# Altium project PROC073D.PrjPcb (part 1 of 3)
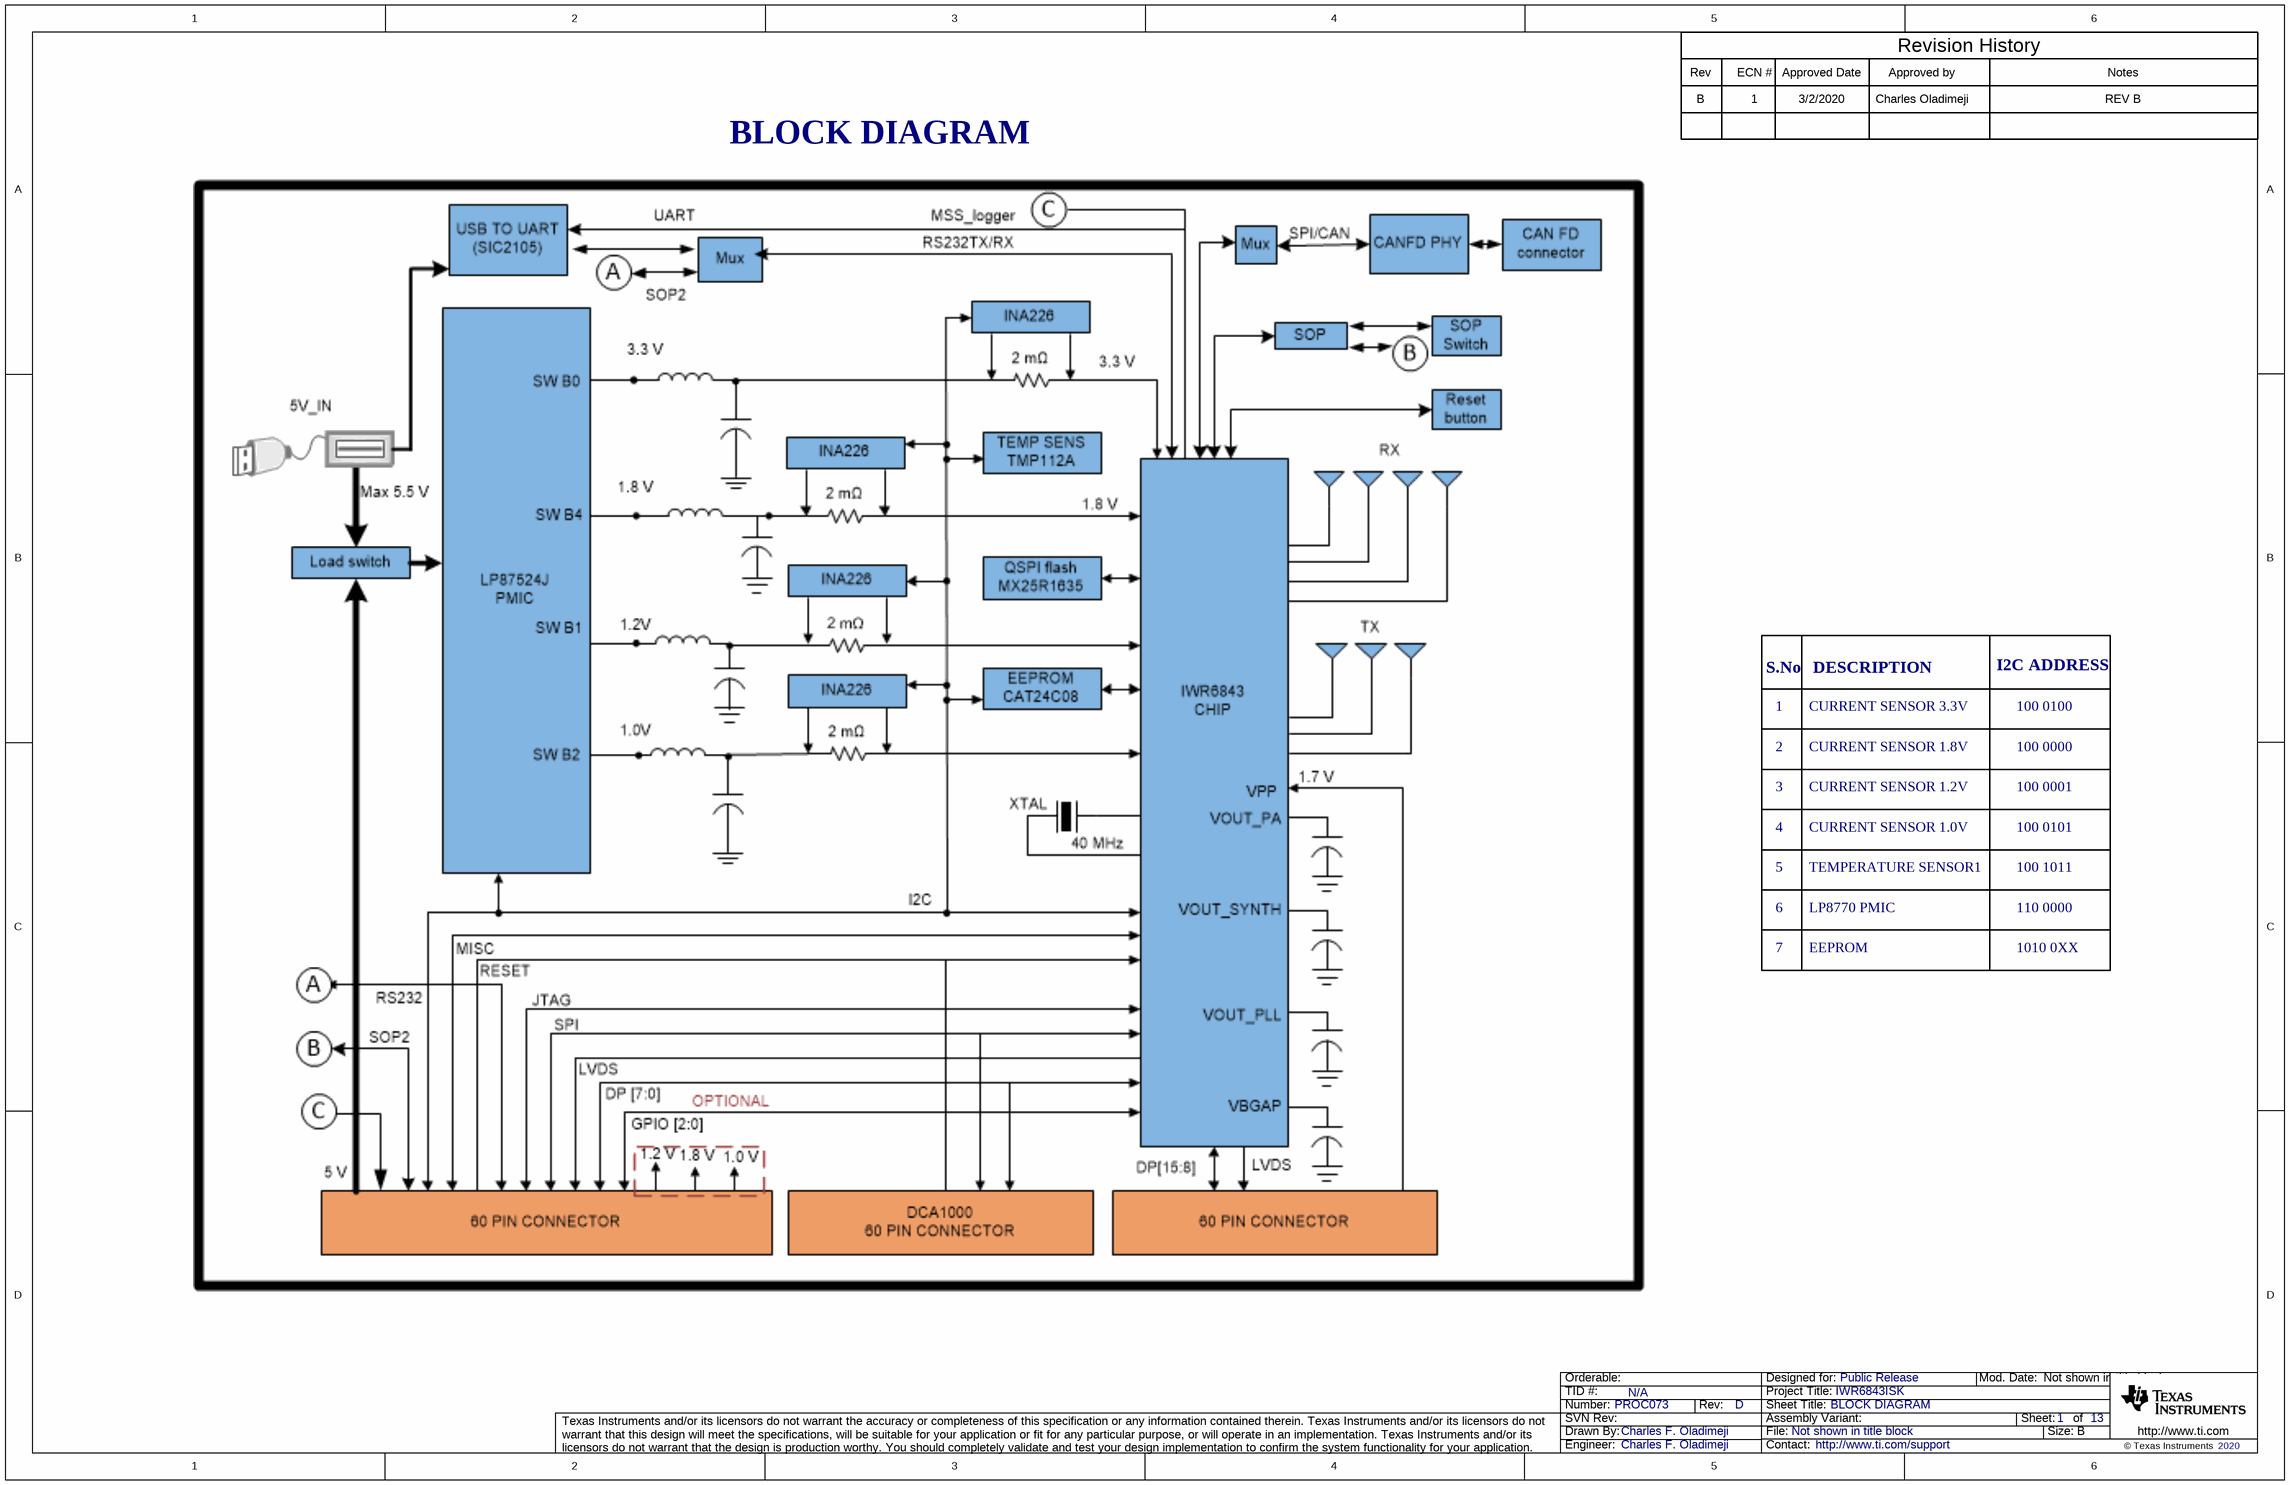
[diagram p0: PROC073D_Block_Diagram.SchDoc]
CopyrightYear: 2020; PCB_Layout: Tessolve; PCB_Rev: D; PRJ_Customer: Public Release; PRJ_Engineer: Charles F. Oladimeji; PRJ_Number: PROC073; PRJ_Title: IWR6843ISK; SCH_Rev: D; TechSupport: http://www.ti.com/support; TID: N/A
13 sheets, 431 parts. Net scope: flat (ports and power ports of the same name join across sheets).
Board file: PROC073D_PCB.PcbDoc
Sheets:
  PROC073D_Block_Diagram.SchDoc
  PROC073D_Table_Of_Contents.SchDoc
  PROC073D_PMIC.SchDoc
  PROC073D_IWR6843_Chip.SchDoc
  PROC073D_Decoupling_caps.SchDoc
  PROC073D_QSPI_Flash_section.SchDoc
  PROC073D_HD_Connector_60Pin.SchDoc
  PROC073D_Temp_Current_sensor.SchDoc
  PROC073D_Flash_USB_To_UART.SchDoc
  PROC073D_HD_DCA_Conn.SchDoc
  PROC073D_SOP_Ctrl.SchDoc
  PROC073D_Can_Interface.SchDoc
  PROC073D_EVM_Hardware.SchDoc

## Sheet PROC073D_Block_Diagram.SchDoc: BLOCK DIAGRAM
size 431 x 279 mm; Date: Not shown in title block; ApprovedBy: Not shown in title block; CheckedBy: Not shown in title block; Author: Not shown in title block; CompanyName: Not shown in title block; DrawnBy: Charles F. Oladimeji; Engineer: Not shown in title block; Organization: Not shown in title block; Address1: Not shown in title block; Address2: Not shown in title block; Address3: Not shown in title block; Address4: Not shown in title block; DocumentNumber: 1; Revision: Use project parameter SCH_Rev; SheetNumber: 1; SheetTotal: 13; PageSetup: Record=PageOptions¦CenterHorizontal=True¦CenterVertical=True¦PrintScale=1.00¦XCorrection=1.00¦YCorrection=1.00¦PrintKind=0¦BorderSize=5000000¦LeftOffset=0¦BottomOffset=0¦Orientation=2¦PaperLength=1000¦PaperWidth=1000¦Scale=100¦PaperSource=15¦PrintQuality=600¦MediaType=1¦DitherType=10¦PaperKind=Letter¦PrintScaleMode=1

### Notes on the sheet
- Rev
- B
- ECN #
- 1
- Approved Date
- 3/2/2020
- Approved by
- Charles Oladimeji
- Revision History
- Notes
- REV B
- BLOCK DIAGRAM
- S.No
- DESCRIPTION
- I2C ADDRESS
- 2
- CURRENT SENSOR 3.3V
- CURRENT SENSOR 1.8V
- 100 0100
- 100 0000
- 3
- 4
- CURRENT SENSOR 1.2V
- CURRENT SENSOR 1.0V
- 100 0001
- 100 0101
- 5
- TEMPERATURE SENSOR1
- 100 1011
- 6
- 7
- LP8770 PMIC
- EEPROM
- 1010 0XX
- 110 0000

## Sheet PROC073D_Table_Of_Contents.SchDoc: TABLE OF CONTENTS
size 431 x 279 mm; Date: Not shown in title block; ApprovedBy: Not shown in title block; CheckedBy: Not shown in title block; Author: Not shown in title block; CompanyName: Not shown in title block; DrawnBy: Charles F. Oladimeji; Engineer: Not shown in title block; Organization: Not shown in title block; Address1: Not shown in title block; Address2: Not shown in title block; Address3: Not shown in title block; Address4: Not shown in title block; DocumentNumber: 2; Revision: Use project parameter SCH_Rev; SheetNumber: 2; SheetTotal: 13; PageSetup: Record=PageOptions¦CenterHorizontal=True¦CenterVertical=True¦PrintScale=1.00¦XCorrection=1.00¦YCorrection=1.00¦PrintKind=0¦BorderSize=5000000¦LeftOffset=0¦BottomOffset=0¦Orientation=2¦PaperLength=1000¦PaperWidth=1000¦Scale=100¦PaperSource=15¦PrintQuality=600¦MediaType=1¦DitherType=10¦PaperKind=Letter¦PrintScaleMode=1
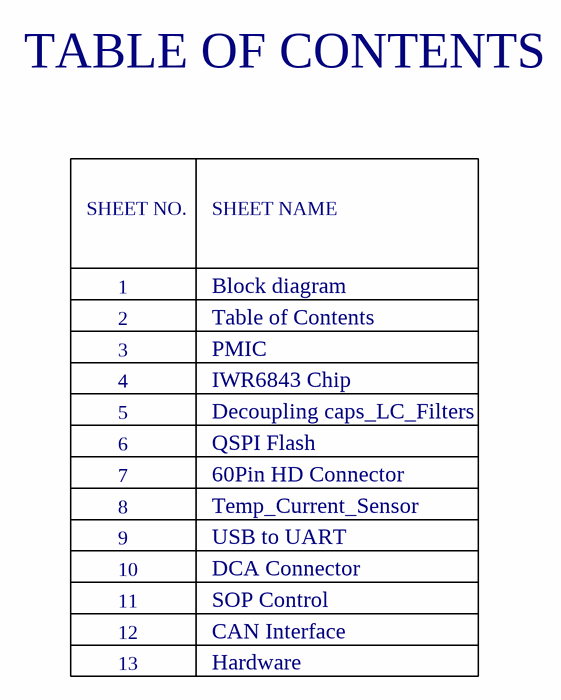
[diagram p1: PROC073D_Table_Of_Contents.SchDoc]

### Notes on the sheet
- TABLE OF CONTENTS
- SHEET NO.
- SHEET NAME
- 1
- 2
- 3
- Table of Contents
- Block diagram
- PMIC
- 4
- 5
- IWR6843 Chip
- Decoupling caps_LC_Filters
- 7
- 8
- 6
- QSPI Flash
- 60Pin HD Connector
- Temp_Current_Sensor
- 9
- 10
- USB to UART
- DCA Connector
- 11
- 12
- 13
- SOP Control
- CAN Interface
- Hardware

## Sheet PROC073D_PMIC.SchDoc: PMIC
size 431 x 279 mm; Date: Not shown in title block; ApprovedBy: Not shown in title block; CheckedBy: Not shown in title block; Author: Not shown in title block; CompanyName: Not shown in title block; DrawnBy: Charles F. Oladimeji; Engineer: Not shown in title block; Organization: Not shown in title block; Address1: Not shown in title block; Address2: Not shown in title block; Address3: Not shown in title block; Address4: Not shown in title block; DocumentNumber: 3; Revision: Use project parameter SCH_Rev; SheetNumber: 3; SheetTotal: 13; PageSetup: Record=PageOptions¦CenterHorizontal=True¦CenterVertical=True¦PrintScale=1.00¦XCorrection=1.00¦YCorrection=1.00¦PrintKind=0¦BorderSize=5000000¦LeftOffset=0¦BottomOffset=0¦Orientation=2¦PaperLength=1000¦PaperWidth=1000¦Scale=100¦PaperSource=15¦PrintQuality=600¦MediaType=1¦DitherType=10¦PaperKind=Letter¦PrintScaleMode=1
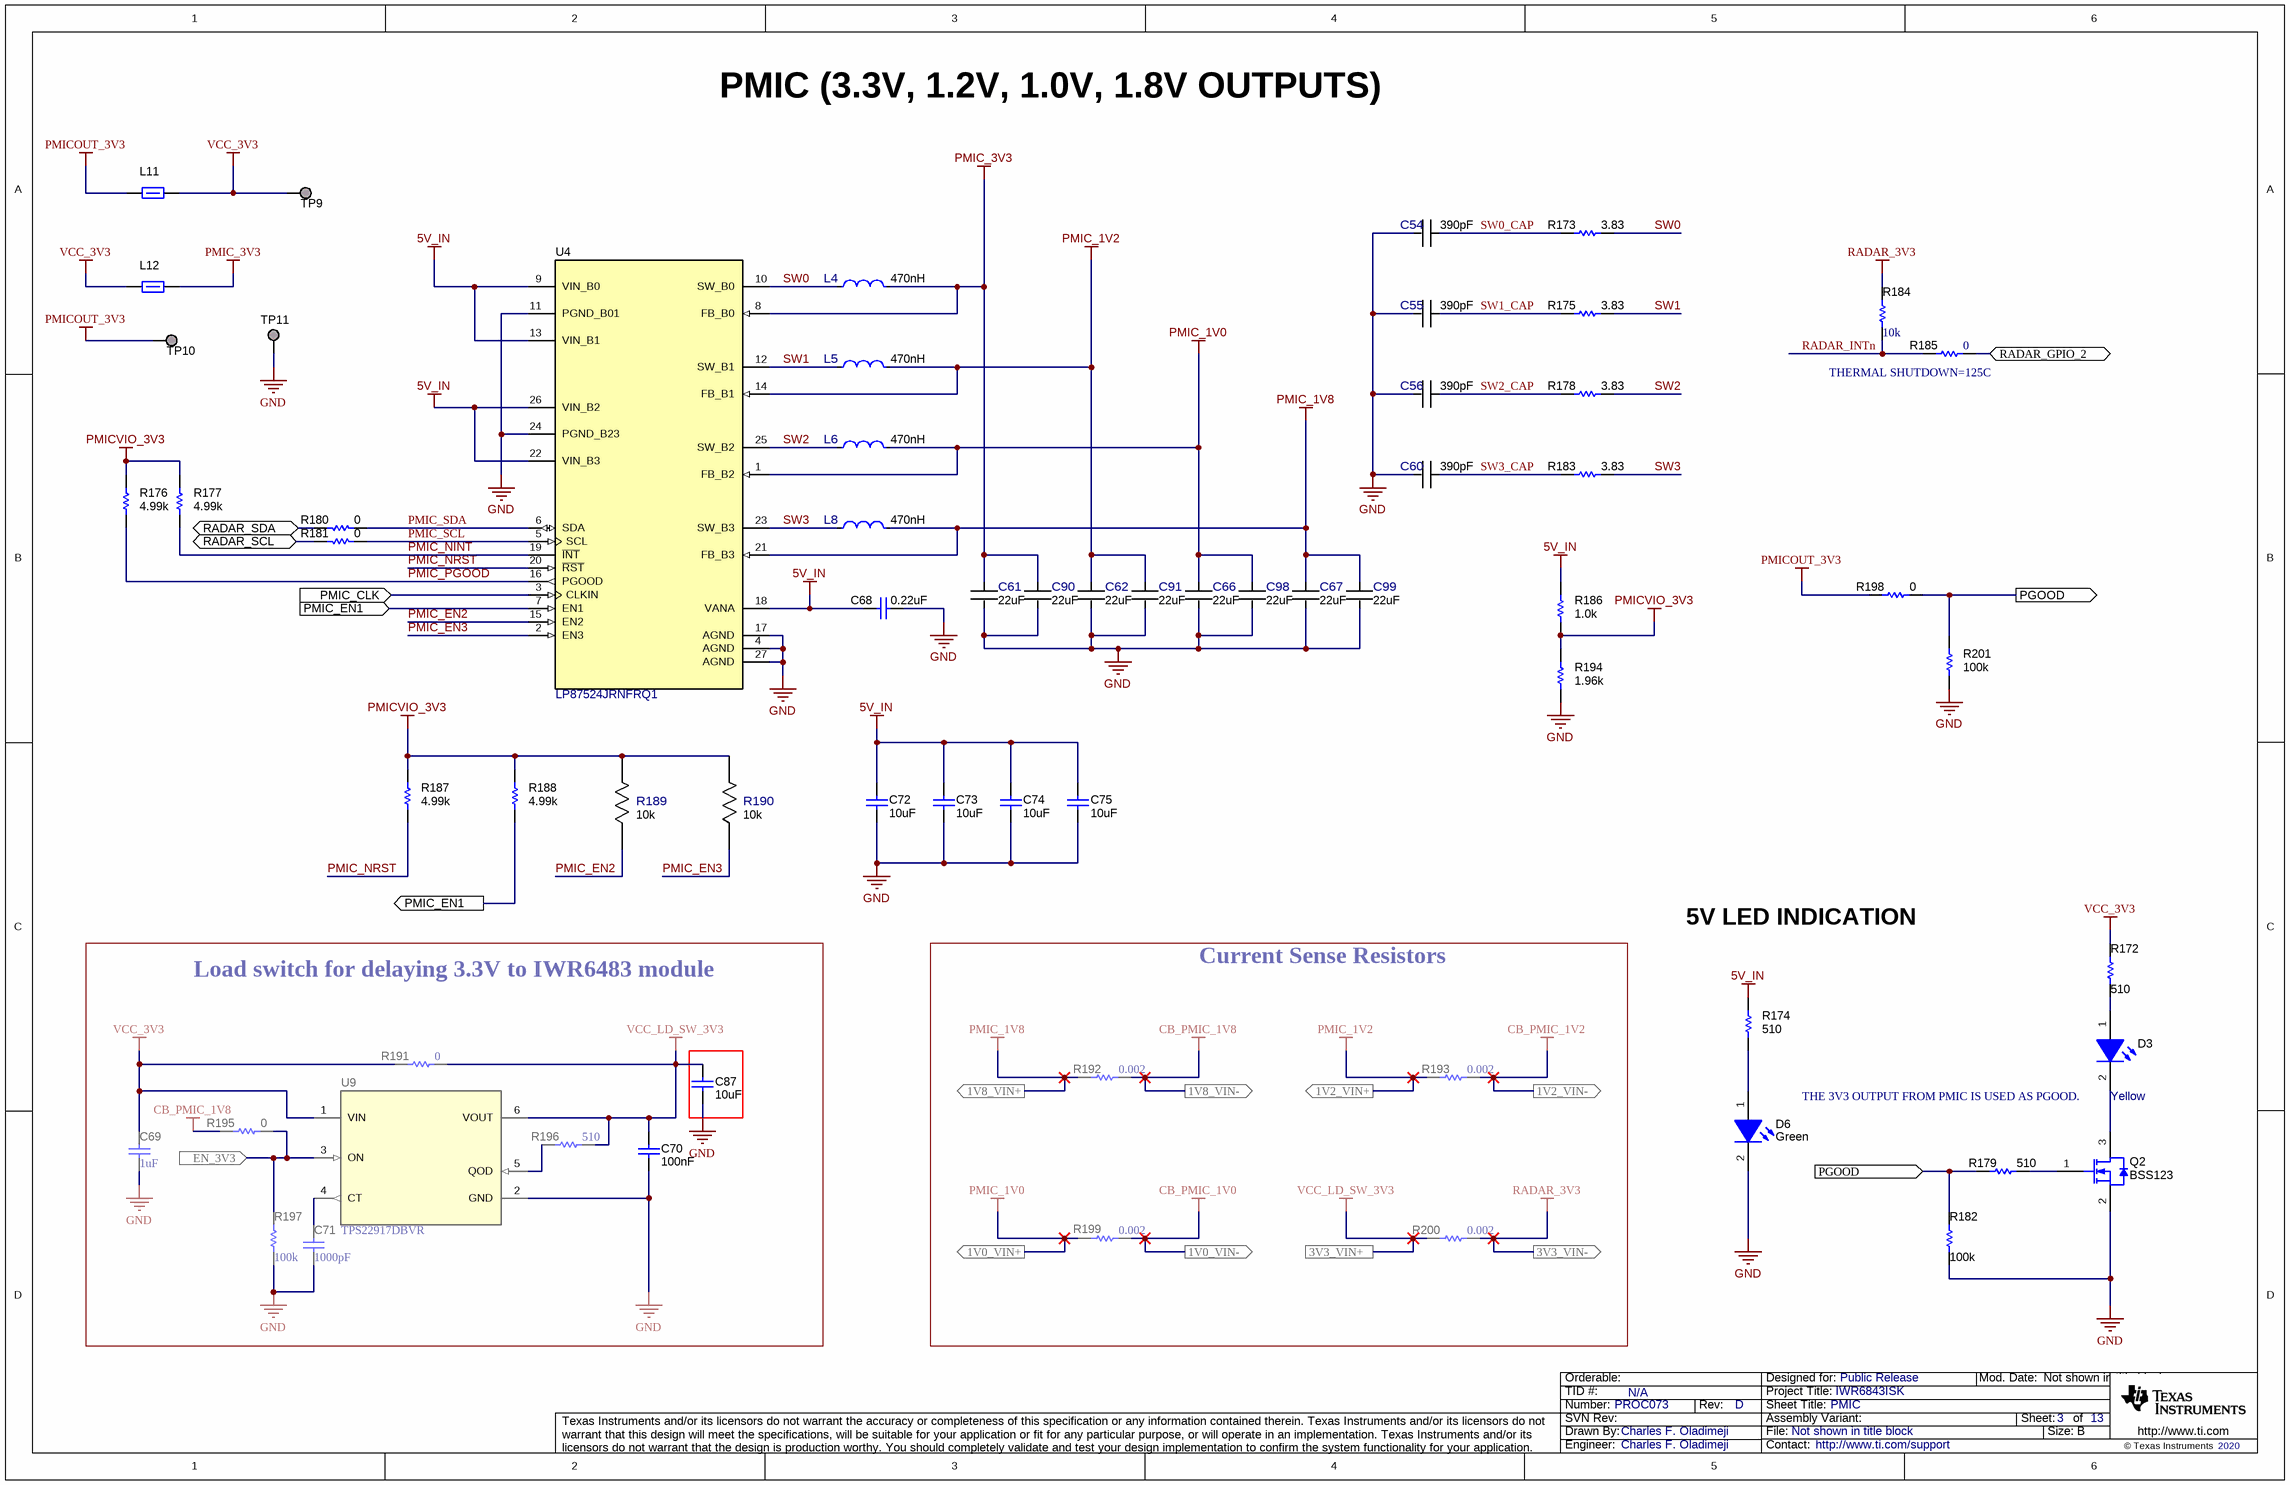
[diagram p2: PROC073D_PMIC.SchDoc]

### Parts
C54  Cap_F: 390pF  [FP-TMK063CG391JT-F_0201 (0603 Metric)-IPC_C]  (hidden comment: TMK063CG391JT-F)
C55  Cap_F: 390pF  [FP-TMK063CG391JT-F_0201 (0603 Metric)-IPC_C]  (hidden comment: TMK063CG391JT-F)
C56  Cap_F: 390pF  [FP-TMK063CG391JT-F_0201 (0603 Metric)-IPC_C]  (hidden comment: TMK063CG391JT-F)
C60  Cap_F: 390pF  [FP-TMK063CG391JT-F_0201 (0603 Metric)-IPC_C]  (hidden comment: TMK063CG391JT-F)
C61  Cap_F: 22uF  [FP-CL05A226MQ5N6J8_0402 (1005 Metric)-IPC_C]  (hidden comment: CL05A226MQ5N6J8)
C62  Cap_F: 22uF  [FP-CL05A226MQ5N6J8_0402 (1005 Metric)-IPC_C]  (hidden comment: CL05A226MQ5N6J8)
C66  Cap_F: 22uF  [FP-CL05A226MQ5N6J8_0402 (1005 Metric)-IPC_C]  (hidden comment: CL05A226MQ5N6J8)
C67  Cap_F: 22uF  [FP-CL05A226MQ5N6J8_0402 (1005 Metric)-IPC_C]  (hidden comment: CL05A226MQ5N6J8)
C68  value 0.22uF  [0201_033L]  (hidden comment: LMK063BJ224MP-F)
C69  ValueDisplayed: 1uF  [0603]  (hidden comment: CL10B105KQ8NNNC)
C70  Cap_F: 100nF  [0603]  (hidden comment: C0603C104J5RACTU)
C71  ValueDisplayed: 1000pF  [0402]  (hidden comment: CGA2B3X7S2A102K050BB)
C72  value 10uF  [0402_070]  (hidden comment: CL05A106MP5NUNC)
C73  value 10uF  [0402_070]  (hidden comment: CL05A106MP5NUNC)
C74  value 10uF  [0402_070]  (hidden comment: CL05A106MP5NUNC)
C75  value 10uF  [0402_070]  (hidden comment: CL05A106MP5NUNC)
C87  ValueDisplayed: 10uF  [0603S]  (hidden comment: GRT188R61A106KE13D)
C90  Cap_F: 22uF  [FP-CL05A226MQ5N6J8_0402 (1005 Metric)-IPC_C]  (hidden comment: CL05A226MQ5N6J8)
C91  Cap_F: 22uF  [FP-CL05A226MQ5N6J8_0402 (1005 Metric)-IPC_C]  (hidden comment: CL05A226MQ5N6J8)
C98  Cap_F: 22uF  [FP-CL05A226MQ5N6J8_0402 (1005 Metric)-IPC_C]  (hidden comment: CL05A226MQ5N6J8)
C99  Cap_F: 22uF  [FP-CL05A226MQ5N6J8_0402 (1005 Metric)-IPC_C]  (hidden comment: CL05A226MQ5N6J8)
D3  value Yellow  [TLMx1000_Yellow]  (hidden comment: TLMY1000-GS08)
D6  Color: Green  [APHHS1005_Green]  (hidden comment: APHHS1005CGCK)
L4  Ind_H: 470nH  [FP-MCKK2012TR47M_0805 (2012 Metric)-IPC_C]  (hidden comment: MCKK2012TR47M)
L5  Ind_H: 470nH  [FP-MCKK2012TR47M_0805 (2012 Metric)-IPC_C]  (hidden comment: MCKK2012TR47M)
L6  Ind_H: 470nH  [FP-MCKK2012TR47M_0805 (2012 Metric)-IPC_C]  (hidden comment: MCKK2012TR47M)
L8  Ind_H: 470nH  [FP-MCKK2012TR47M_0805 (2012 Metric)-IPC_C]  (hidden comment: MCKK2012TR47M)
L11  BLM15PD300SZ1D  [0402L]  (value not drawn)
L12  BLM15PD300SZ1D  [0402L]  (value not drawn)
Q2  BSS123  [SOT-23]
R172  ValueDisplayed: 510  [0402L]  (hidden comment: ERJ-2GEJ511X)
R173  Res_ohm: 3.83  [FP-RC0402FR-073R83L_0402 (1005 Metric)-IPC_C]  (hidden comment: RC0402FR-073R83L)
R174  value 510  [0201L]  (hidden comment: RC0201JR-07510RL)
R175  Res_ohm: 3.83  [FP-RC0402FR-073R83L_0402 (1005 Metric)-IPC_C]  (hidden comment: RC0402FR-073R83L)
R176  value 4.99k  [0201L]  (hidden comment: RC0201FR-074K99L)
R177  value 4.99k  [0201L]  (hidden comment: RC0201FR-074K99L)
R178  Res_ohm: 3.83  [FP-RC0402FR-073R83L_0402 (1005 Metric)-IPC_C]  (hidden comment: RC0402FR-073R83L)
R179  ValueDisplayed: 510  [0402L]  (hidden comment: ERJ-2GEJ511X)
R180  Res_ohm: 0  [FP-RC0201JR-070RL_0201 (0603 Metric)-MFG]  (hidden comment: RC0201JR-070RL)
R181  Res_ohm: 0  [FP-RC0201JR-070RL_0201 (0603 Metric)-MFG]  (hidden comment: RC0201JR-070RL)
R182  ValueDisplayed: 100k  [0402L]  (hidden comment: CRCW0402100KFKED)
R183  Res_ohm: 3.83  [FP-RC0402FR-073R83L_0402 (1005 Metric)-IPC_C]  (hidden comment: RC0402FR-073R83L)
R184  value 10k  [0402]  (hidden comment: CRCW040210K0JNED)
R185  Res_ohm: 0  [0402]  (hidden comment: CRCW04020000Z0ED)
R186  value 1.0k  [0201L]  (hidden comment: RC0201JR-071KL)
R187  value 4.99k  [0201L]  (hidden comment: RC0201FR-074K99L)
R188  value 4.99k  [0201L]  (hidden comment: RC0201FR-074K99L)
R189  Res_ohm: 10k  [FP-RR0306P-103-D_0201-IPC_C]  (hidden comment: RR0306P-103-D)
R190  Res_ohm: 10k  [FP-RR0306P-103-D_0201-IPC_C]  (hidden comment: RR0306P-103-D)
R191  ValueDisplayed: 0  [0603]  (hidden comment: RCS06030000Z0EA)
R192  ValueDisplayed: 0.002  [1206]  (hidden comment: PMR18EZPFV2L00)
R193  ValueDisplayed: 0.002  [1206]  (hidden comment: PMR18EZPFV2L00)
R194  value 1.96k  [0201L]  (hidden comment: RC0201FR-071K96L)
R195  ValueDisplayed: 0  [0603]  (hidden comment: MCT06030Z0000ZP500)
R196  ValueDisplayed: 510  [0402]  (hidden comment: CRCW0402510RJNED)
R197  ValueDisplayed: 100k  [0402]  (hidden comment: ERJ-2RKF1003X)
R198  Res_ohm: 0  [FP-RC0201JR-070RL_0201 (0603 Metric)-MFG]  (hidden comment: RC0201JR-070RL)
R199  ValueDisplayed: 0.002  [1206]  (hidden comment: PMR18EZPFV2L00)
R200  ValueDisplayed: 0.002  [1206]  (hidden comment: PMR18EZPFV2L00)
R201  value 100k  [0201L]  (hidden comment: CRCW0201100KFKED)
TP9  TESTPOINT  [TP_25MIL-SMT]  (value not drawn)  (no BOM)
TP10  TESTPOINT  [TP_25MIL-SMT]  (value not drawn)  (no BOM)
TP11  TESTPOINT  [TP_VIA_060RND040]  (value not drawn)  (no BOM)
U4  LP87524JRNFRQ1  [RNF0026C]
U9  TPS22917DBVR  [DBV0006A_N]

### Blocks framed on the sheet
Load switch for delaying 3.3V to IWR6483 module: C69-C71 C87 R191 R195-R197 U9
Current Sense Resistors: R192 R193 R199 R200

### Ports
1V0_VIN+ (out), 1V0_VIN- (out), 1V2_VIN+ (out), 1V2_VIN- (out), 1V8_VIN+ (out), 1V8_VIN- (out), 3V3_VIN+, 3V3_VIN- (out), EN_3V3 (in), PGOOD (in), PGOOD (out), PMIC_CLK (in), PMIC_EN1 (in), PMIC_EN1 (out), RADAR_GPIO_2 (bidir), RADAR_SCL (bidir), RADAR_SDA (bidir)

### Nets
5V_IN: C68.1 C72.1 C73.1 C74.1 C75.1 R174.1 R186.2 U4.9(VIN_B0) U4.13(VIN_B1) U4.18(VANA) U4.22(VIN_B3) U4.26(VIN_B2)
CB_PMIC_1V0: R199.2 ; port 1V0_VIN-
CB_PMIC_1V2: R193.2 ; port 1V2_VIN-
CB_PMIC_1V8: R192.2 R195.1 ; port 1V8_VIN-
GND: C54.2 C55.2 C56.2 C60.2 C61.2 C62.2 C66.2 C67.2 C68.2 C69.2 C70.2 C71.2 C72.2 C73.2 C74.2 C75.2 C87.1 C90.2 C91.2 C98.2 C99.2 D6.2(K) Q2.2(S) R182.1 R194.1 R197.1 R201.1 TP11.1 U4.4(AGND) U4.11(PGND_B01) U4.17(AGND) U4.24(PGND_B23) U4.27(AGND) U9.2(GND)
PMIC_1V0: C66.1 C98.1 L6.1 R199.1 U4.1(FB_B2) ; port 1V0_VIN+
PMIC_1V2: C62.1 C91.1 L5.1 R193.1 U4.14(FB_B1) ; port 1V2_VIN+
PMIC_1V8: C67.1 C99.1 L8.1 R192.1 U4.21(FB_B3) ; port 1V8_VIN+
PMIC_3V3: C61.1 C90.1 L4.1 L12.2 U4.8(FB_B0)
PMICOUT_3V3: L11.1 R198.2 TP10.1
PMICVIO_3V3: R176.2 R177.2 R186.1 R187.2 R188.2 R189.2 R190.2 R194.2
RADAR_3V3: R184.2 R200.2 ; port 3V3_VIN-
VCC_3V3: C69.1 L11.2 L12.1 R172.2 R191.1 TP9.1 U9.1(VIN)
VCC_LD_SW_3V3: C70.1 C87.2 R191.2 R196.1 R200.1 U9.6(VOUT) ; port 3V3_VIN+
EN_3V3: R195.2 R197.2 U9.3(ON) ; port EN_3V3
PGOOD: R179.1 R182.2 R198.1 R201.2 ; port PGOOD
PMIC_CLK: U4.3(CLKIN) ; port PMIC_CLK
PMIC_EN1: R188.1 U4.7(EN1) ; port PMIC_EN1
PMIC_EN2: R189.1 U4.15(EN2)
PMIC_EN3: R190.1 U4.2(EN3)
PMIC_NINT: R177.1 U4.19(~{INT})
PMIC_NRST: R187.1 U4.20(~{RST})
PMIC_PGOOD: R176.1 U4.16(PGOOD)
PMIC_SCL: R181.2 U4.5(SCL)
PMIC_SDA: R180.2 U4.6(SDA)
RADAR_GPIO_2: R185.2 ; port RADAR_GPIO_2
RADAR_INTn: R184.1 R185.1
RADAR_SCL: R181.1 ; port RADAR_SCL
RADAR_SDA: R180.1 ; port RADAR_SDA
SW0: L4.2 R173.2 U4.10(SW_B0)
SW0_CAP: C54.1 R173.1
SW1: L5.2 R175.2 U4.12(SW_B1)
SW1_CAP: C55.1 R175.1
SW2: L6.2 R178.2 U4.25(SW_B2)
SW2_CAP: C56.1 R178.1
SW3: L8.2 R183.2 U4.23(SW_B3)
SW3_CAP: C60.1 R183.1
NetC71_1: C71.1 U9.4(CT)
NetD3_1: D3.1(A) R172.1
NetD3_2: D3.2(K) Q2.3(D)
NetD6_1: D6.1(A) R174.2
NetQ2_1: Q2.1(G) R179.2
NetR196_2: R196.2 U9.5(QOD)

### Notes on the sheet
- PMIC (3.3V, 1.2V, 1.0V, 1.8V OUTPUTS)
- (near R185) THERMAL SHUTDOWN=125C
- 5V LED INDICATION
- THE 3V3 OUTPUT FROM PMIC IS USED AS PGOOD.

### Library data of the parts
C54-C56 C60 = CMP-0086438-1: CAP CER 390PF 25V C0G/NP0 0201; Manufacturer: Taiyo Yuden; AEC Qualified: No; SizeZ_mm: 0.33mm; Symbol Name: SYM-TMK063CG391JT-F; TempCo: 30ppm/°C; Tolerance_%: 5%
C61 C62 C66 C67 C90 C91 C98 C99 = CMP-0086447-1: CAP CER 22UF 6.3V X5R 0402; Manufacturer: Samsung Electro-Mechanics; AEC Qualified: No; SizeZ_mm: 0.55mm; Symbol Name: SYM-CL05A226MQ5N6J8; TempCo: 15%; Tolerance_%: 20%
C68 = CMP-0009781-1: CAP, CERM, 0.22 uF, 10 V, +/- 20%, X5R, 0201; Manufacturer: Taiyo Yuden; AEC Category: Q200; AEC Qualified: N; Cap_Case: 0201; Cap_F: 220nF; SizeArea_mm2: 0.18; SizeAreaWB_mm2: 2.08; SizeX_mm: 0.6; SizeY_mm: 0.3; SizeZ_mm: 0.33; TaMax_C: 85°C; TaMin_C: -55°C; U/M: EA; Value1: Unknown; Value2: 10V
C69 = CMP-0007111-4: CAP, CERM, 1 uF, 6.3 V, +/- 10%, X7R, 0603; Manufacturer: Samsung Electro-Mechanics; TaMin_C: -55°C; Polarized: N; SizeAreaWB_mm2: 4.68; Value1: Unknown; U/M: EA; Value: 1uF; TaMax_C: 125°C; SizeZ_mm: 1; SizeX_mm: 1.6; SizeY_mm: 0.8; Value2: 6.3V; SizeArea_mm2: 1.28; CompType: Capacitor; Cap_F: 1µF; AEC Category: Q200
C70 = CMP-0006858-4: CAP, CERM, 0.1 uF, 50 V, +/- 5%, X7R, 0603; Manufacturer: Kemet; TaMin_C: -55°C; Polarized: N; SizeAreaWB_mm2: 4.68; Value1: Unknown; U/M: EA; Value: 0.1uF; TaMax_C: 125°C; SizeZ_mm: 1; SizeX_mm: 1.6; SizeY_mm: 0.8; Value2: 50V; SizeArea_mm2: 1.28; AEC Category: Q200
C71 = CMP-0006332-2: CAP, CERM, 1000 pF, 100 V, +/- 10%, X7S, AEC-Q200 Grade 1, 0402; Manufacturer: TDK; TaMin_C: -55°C; ESR_ohm: 2.71151; Polarized: N; SizeAreaWB_mm2: 3; Value1: 2.71151 ohm; U/M: EA; Value: 1000pF; TaMax_C: 125°C; SizeZ_mm: 0.6; SizeX_mm: 1; SizeY_mm: 0.5; Value2: 100V; AEC Qualified: Y; Cap_F: 1nF; IRMS_A: 2.64589dA; AEC Category: Q200
C72-C75 = CMP-0006339-4: CAP, CERM, 10 uF, 10 V, +/- 20%, X5R, 0402; Manufacturer: Samsung Electro-Mechanics; AEC Category: Q200; AEC Qualified: N; Cap_Case: 0402; Cap_F: 10µF; SizeArea_mm2: 0.5; SizeAreaWB_mm2: 3; SizeX_mm: 1; SizeZ_mm: 0.6; TaMax_C: 85°C; TaMin_C: -55°C; U/M: EA; Value1: Unknown; Value2: 10V
C87 = CMP-0007497-5: CAP, CERM, 10 uF, 10 V, +/- 10%, X5R, 0603; Manufacturer: MuRata; Polarized: N; Value: 10uF; U/M: EA; Cap_F: 10µF; Tolerance_%: 20%; Value1: Unknown; VDC_V: 10V; TempCo: X7R; TaMin_C: -55°C; TaMax_C: 125°C; Cap_Case: 0603; SizeArea_mm2: 1.28; SizeAreaWB_mm2: 4.68; SizeX_mm: 1.6; SizeY_mm: 0.8; SizeZ_mm: 1; AEC Category: Q200
D3 = CMP-0078196-2: LED, Yellow, SMD; Manufacturer: Vishay-Semiconductor; Tjmax_C: 120°C; SizeAreaWB_mm2: 4.68; Vr_V: 6V; Power_TotalModule: 40mW; Angle: 160; SizeArea_mm2: 1.28; Ir_A: 10µA; SizeZ_mm: 0.65; Io_A: 2mA; Vf_V: 1.8V; SizeY_mm: 0.8; Value1: .04W; SizeX_mm: 1.6; Type: AlInGaP
D6 = CMP-0067682-2: LED, Green, SMD; Manufacturer: Kingbright; Angle: 120.0; Power_TotalModule: 75mW; SizeZ_mm: 0.6; Vf_V: 2.1V; Vr_V: 5V; Io_A: 20mA; Ir_A: 10µA; SizeArea_mm2: 0.5; SizeAreaWB_mm2: 3.0; SizeX_mm: 1.0; Tjmax_C: 85°C; Value1: 0.075W
L4-L6 L8 = CMP-0087178-1: FIXED IND 470NH 4.5A 39 MOHM SMD; Manufacturer: Taiyo Yuden; AEC Qualified: No; DCR_ohm: 0.032; Irms: 3.1A; Material: Metal; SizeZ_mm: 1mm; Symbol Name: SYM-MCKK2012TR47M
L11 L12 = CMP-0078934-1: Inductor, Ferrite Bead, Ferrite, 2.2 A, 0.035 ohm, AEC-Q200 Grade 1, SMD; Manufacturer: MuRata; AEC Category: Q200; AEC Grade: 1; AEC Qualified: Y; DCR_ohm: 0.035; Imax_A: 2.2A; SizeArea_mm2: 0.5; SizeAreaWB_mm2: 3; SizeZ_mm: 0.6
Q2 = CMP-0000947-2: MOSFET, N-CH, 100 V, 0.17 A, SOT-23; Alternate Manufacturer: None; Manufacturer: Fairchild Semiconductor; SizeZ_mm: 1.1; ChType: N; Value2: 1.8 nC; Value1: 1; VdsMax_V: 100V; SizeX_mm: 2.5; SizeY_mm: 3; Vgs_V: 20V; Value: 100V; Rdson45_ohm: 10; SizeArea_mm2: 7.5; AEC Category: Q101; IdsMax_A: 1.7dA; SizeAreaWB_mm2: 14; U/M: EA; QgTyp_nC: 1.8
R172 R179 = CMP-0078212-1: RES, 510, 5%, 0.1 W, AEC-Q200 Grade 0, 0402; Manufacturer: Panasonic; Value_Code: 510R; SizeArea_mm2: 0.5; AEC Qualified: Y; AEC Category: Q200; Value: 510; SizeZ_mm: 0.6; EIA_Code: E24; TempCo: 200 ppm/C; AEC Grade: 0; Power_W: 100mW; VDC_V: 50V; Value2: 0.1W; U/M: EA; SizeX_mm: 1
R173 R175 R178 R183 = CMP-0086444-2: RES Thick Film SMD 3.83Ω 1% 1/16W 0402 200ppm/°C; Manufacturer: Yageo; AEC Qualified: No; Power_W: 63mW; VDC_V: 50V; SizeZ_mm: 0.4mm
R174 = CMP-0027137-1: RES, 510, 5%, 0.05 W, 0201; Manufacturer: Yageo America; AEC Category: Q200; AEC Qualified: N; EIA_Code: E24; Power_W: 50mW; SizeArea_mm2: 0.18; SizeX_mm: 0.6; SizeY_mm: 0.3; SizeZ_mm: 0.26; TempCo: 200 ppm/C; U/M: EA; Value2: 0.05W; Value_Code: 510R; VDC_V: 25V
R176 R177 R187 R188 = CMP-0027745-1: RES, 4.99 k, 1%, 0.05 W, 0201; Manufacturer: Yageo America; AEC Category: Q200; AEC Qualified: N; EIA_Code: E96; Power_W: 50mW; SizeArea_mm2: 0.18; SizeX_mm: 0.6; SizeY_mm: 0.3; SizeZ_mm: 0.26; TempCo: 200 ppm/C; U/M: EA; Value2: 0.05W; Value_Code: 4k99; VDC_V: 25V
R180 R181 R198 = CMP-0086442-2: RES SMD 0 OHM JUMPER 1/20W 0201; Manufacturer: Yageo; AEC Qualified: No; Power_W: 50mW; SizeZ_mm: 0.26mm; TempCo: 200ppm/°C; Tolerance_%: 5%; VDC_V: 25V
R182 = CMP-0025950-3: RES, 100 k, 1%, 0.063 W, AEC-Q200 Grade 0, 0402; Manufacturer: Vishay-Dale; Power_W: 63mW; TempCo: 100 ppm/C; Value: 100k; EIA_Code: E96; SizeX_mm: 1; SizeY_mm: 0.5; SizeZ_mm: 0.6; Value2: 0.063W; AEC Qualified: Y; VDC_V: 50V; AEC Category: Q200; AEC Grade: 0
R184 = CMP-0026825-5: RES, 10 k, 5%, 0.063 W, AEC-Q200 Grade 0, 0402; Manufacturer: Vishay-Dale; Power_W: 63mW; TempCo: 200 ppm/C; Value_Code: 10k0; EIA_Code: E24; SizeX_mm: 1; SizeY_mm: 0.5; SizeZ_mm: 0.6; Value2: 0.063W; CompType: Resistor; AEC Qualified: Y; VDC_V: 50V; AEC Category: Q200; AEC Grade: 0
R185 = CMP-0026822-3: RES, 0, 5%, 0.063 W, AEC-Q200 Grade 0, 0402; Manufacturer: Vishay-Dale; Power_W: 63mW; TempCo: 200 ppm/C; Value_Code: 0000; Value: 0; EIA_Code: E24; SizeX_mm: 1; SizeY_mm: 0.5; SizeZ_mm: 0.6; Value2: 0.063W; CompType: Resistor; AEC Qualified: Y; VDC_V: 50V; AEC Category: Q200
R186 = CMP-0027052-1: RES, 1.0 k, 5%, 0.05 W, 0201; Manufacturer: Yageo America; AEC Category: Q200; AEC Qualified: N; EIA_Code: E24; Power_W: 50mW; Res_ohm: 1k; SizeArea_mm2: 0.18; SizeX_mm: 0.6; SizeY_mm: 0.3; SizeZ_mm: 0.26; TempCo: 200 ppm/C; U/M: EA; Value2: 0.05W; Value_Code: 1k00; VDC_V: 25V
R189 R190 = CMP-0088002-1: 10 kOhms ±0.5% 0.05W, 1/20W Chip Resistor 0201 (0603 Metric)  Thin Film; Manufacturer: Susumu; AEC Qualified: No; Power_W: 50mW; SizeZ_mm: 0.26mm; Symbol Name: SYM-RR0306P-103-D; TempCo: 25ppm/°C; VDC_V: 15V
R191 = CMP-0081973-1: RES, 0, 0%, 0.25 W, AEC-Q200 Grade 0, 0603; Manufacturer: Vishay-Dale; SizeAreaWB_mm2: 4.68; SizeArea_mm2: 1.28; AEC Qualified: Y; AEC Category: Q200; Value: 0; SizeZ_mm: 1; SizeY_mm: 0.8; Power_W: 250mW; Value2: 0.25W; CompType: Resistor; SizeX_mm: 1.6; INSTALLATION: DNP
R192 R193 R199 R200 = CMP-0081623-1: RES, 0.002, 1%, 1 W, AEC-Q200 Grade 0, 1206; Manufacturer: Rohm; Value_Code: 2L000; SizeAreaWB_mm2: 10.92; SizeArea_mm2: 5.12; AEC Qualified: Y; AEC Category: Q200; Res_ohm: 2m; Value: 0.002; SizeZ_mm: 1.35; Green_REACh: Incomplete; TempCo: 100 ppm/C; AEC Grade: 0; Power_W: 1W; SizeY_mm: 1.6; Green_Lifecycle: Active; SizeX_mm: 3.2
R194 = CMP-0027452-1: RES, 1.96 k, 1%, 0.05 W, 0201; Manufacturer: Yageo America; AEC Category: Q200; AEC Qualified: N; EIA_Code: E96; Power_W: 50mW; SizeArea_mm2: 0.18; SizeX_mm: 0.6; SizeY_mm: 0.3; SizeZ_mm: 0.26; TempCo: 200 ppm/C; U/M: EA; Value2: 0.05W; Value_Code: 1k96; VDC_V: 25V
R195 = CMP-0025884-3: RES, 0, 5%, 0.125 W, 0603; Manufacturer: Vishay/Beyschlag; Power_W: 125mW; TempCo: ppm/C; Value_Code: 0000; U/M: EA; Value: 0; EIA_Code: E24; SizeX_mm: 1.6; SizeY_mm: 0.8; SizeZ_mm: 1; Value2: 0.125W; SizeArea_mm2: 1.28; CompType: Resistor; AEC Qualified: N; AEC Category: Q200; INSTALATION: DNP
R196 = CMP-0026944-3: RES, 510, 5%, 0.063 W, AEC-Q200 Grade 0, 0402; Manufacturer: Vishay-Dale; Power_W: 63mW; TempCo: 200 ppm/C; Value_Code: 510R; Value: 510; EIA_Code: E24; SizeX_mm: 1; SizeY_mm: 0.5; SizeZ_mm: 0.6; Value2: 0.063W; AEC Qualified: Y; VDC_V: 50V; AEC Category: Q200; AEC Grade: 0
R197 = CMP-0026659-1: RES, 100 k, 1%, 0.1 W, 0402; Manufacturer: Panasonic; Power_W: 100mW; TempCo: 100 ppm/C; U/M: EA; Value: 100k; EIA_Code: E96; SizeX_mm: 1; SizeY_mm: 0.5; SizeZ_mm: 0.6; Value2: 0.1W; VDC_V: 50V; AEC Category: Q200
R201 = CMP-0027261-3: RES, 100 k, 1%, 0.05 W, 0201; Manufacturer: Vishay-Dale; AEC Category: Q200; AEC Qualified: N; EIA_Code: E96; Power_W: 50mW; SizeArea_mm2: 0.18; SizeX_mm: 0.6; SizeY_mm: 0.3; SizeZ_mm: 0.26; TempCo: 100 ppm/C; Value2: 0.05W; VDC_V: 30V
TP9-TP11 = CMP-0078143-3: TEST POINT.  No entry in BOM.
U4 = CMP-0079120-2: 4-A + 2.5-A + Two 1.5-A Buck Converters With Integrated Switches, RNF0026C (VQFN-HR-26); Alternate PartNumber: LP87524JRNFTQ1; Alternate Manufacturer: Texas Instruments; SizeAreaWB_mm2: 27.5; SizeZ_mm: 0.9; SizeX_mm: 4; SizeY_mm: 4.5; SizeArea_mm2: 18; CompType: IC; AEC Qualified: Y; AEC Category: Q200
U9 = CMP-0077265-1: 5.5-V, 2-A, 80 mohm Low Leakage Load Switch with RCB and Programmable Rise Time, DBV0006A (SOT-23-6); Alternate PartNumber: TPS22917DBVT; Alternate Manufacturer: Texas Instruments; SizeAreaWB_mm2: 14.82; SizeZ_mm: 1.45; SizeX_mm: 2.8; SizeY_mm: 2.9; SizeArea_mm2: 8.12; CompType: IC; AEC Qualified: N; AEC Category: Q200

## Sheet PROC073D_IWR6843_Chip.SchDoc: IWR6843_CHIP
size 431 x 279 mm; Date: Not shown in title block; ApprovedBy: Not shown in title block; CheckedBy: Not shown in title block; Author: Not shown in title block; CompanyName: Not shown in title block; DrawnBy: Charles F. Oladimeji; Engineer: Not shown in title block; Organization: Not shown in title block; Address1: Not shown in title block; Address2: Not shown in title block; Address3: Not shown in title block; Address4: Not shown in title block; DocumentNumber: 4; Revision: Use project parameter SCH_Rev; SheetNumber: 4; SheetTotal: 13; PageSetup: Record=PageOptions¦CenterHorizontal=True¦CenterVertical=True¦PrintScale=1.00¦XCorrection=1.00¦YCorrection=1.00¦PrintKind=0¦BorderSize=5000000¦LeftOffset=0¦BottomOffset=0¦Orientation=2¦PaperLength=1000¦PaperWidth=1000¦Scale=100¦PaperSource=15¦PrintQuality=600¦MediaType=1¦DitherType=10¦PaperKind=Letter¦PrintScaleMode=1
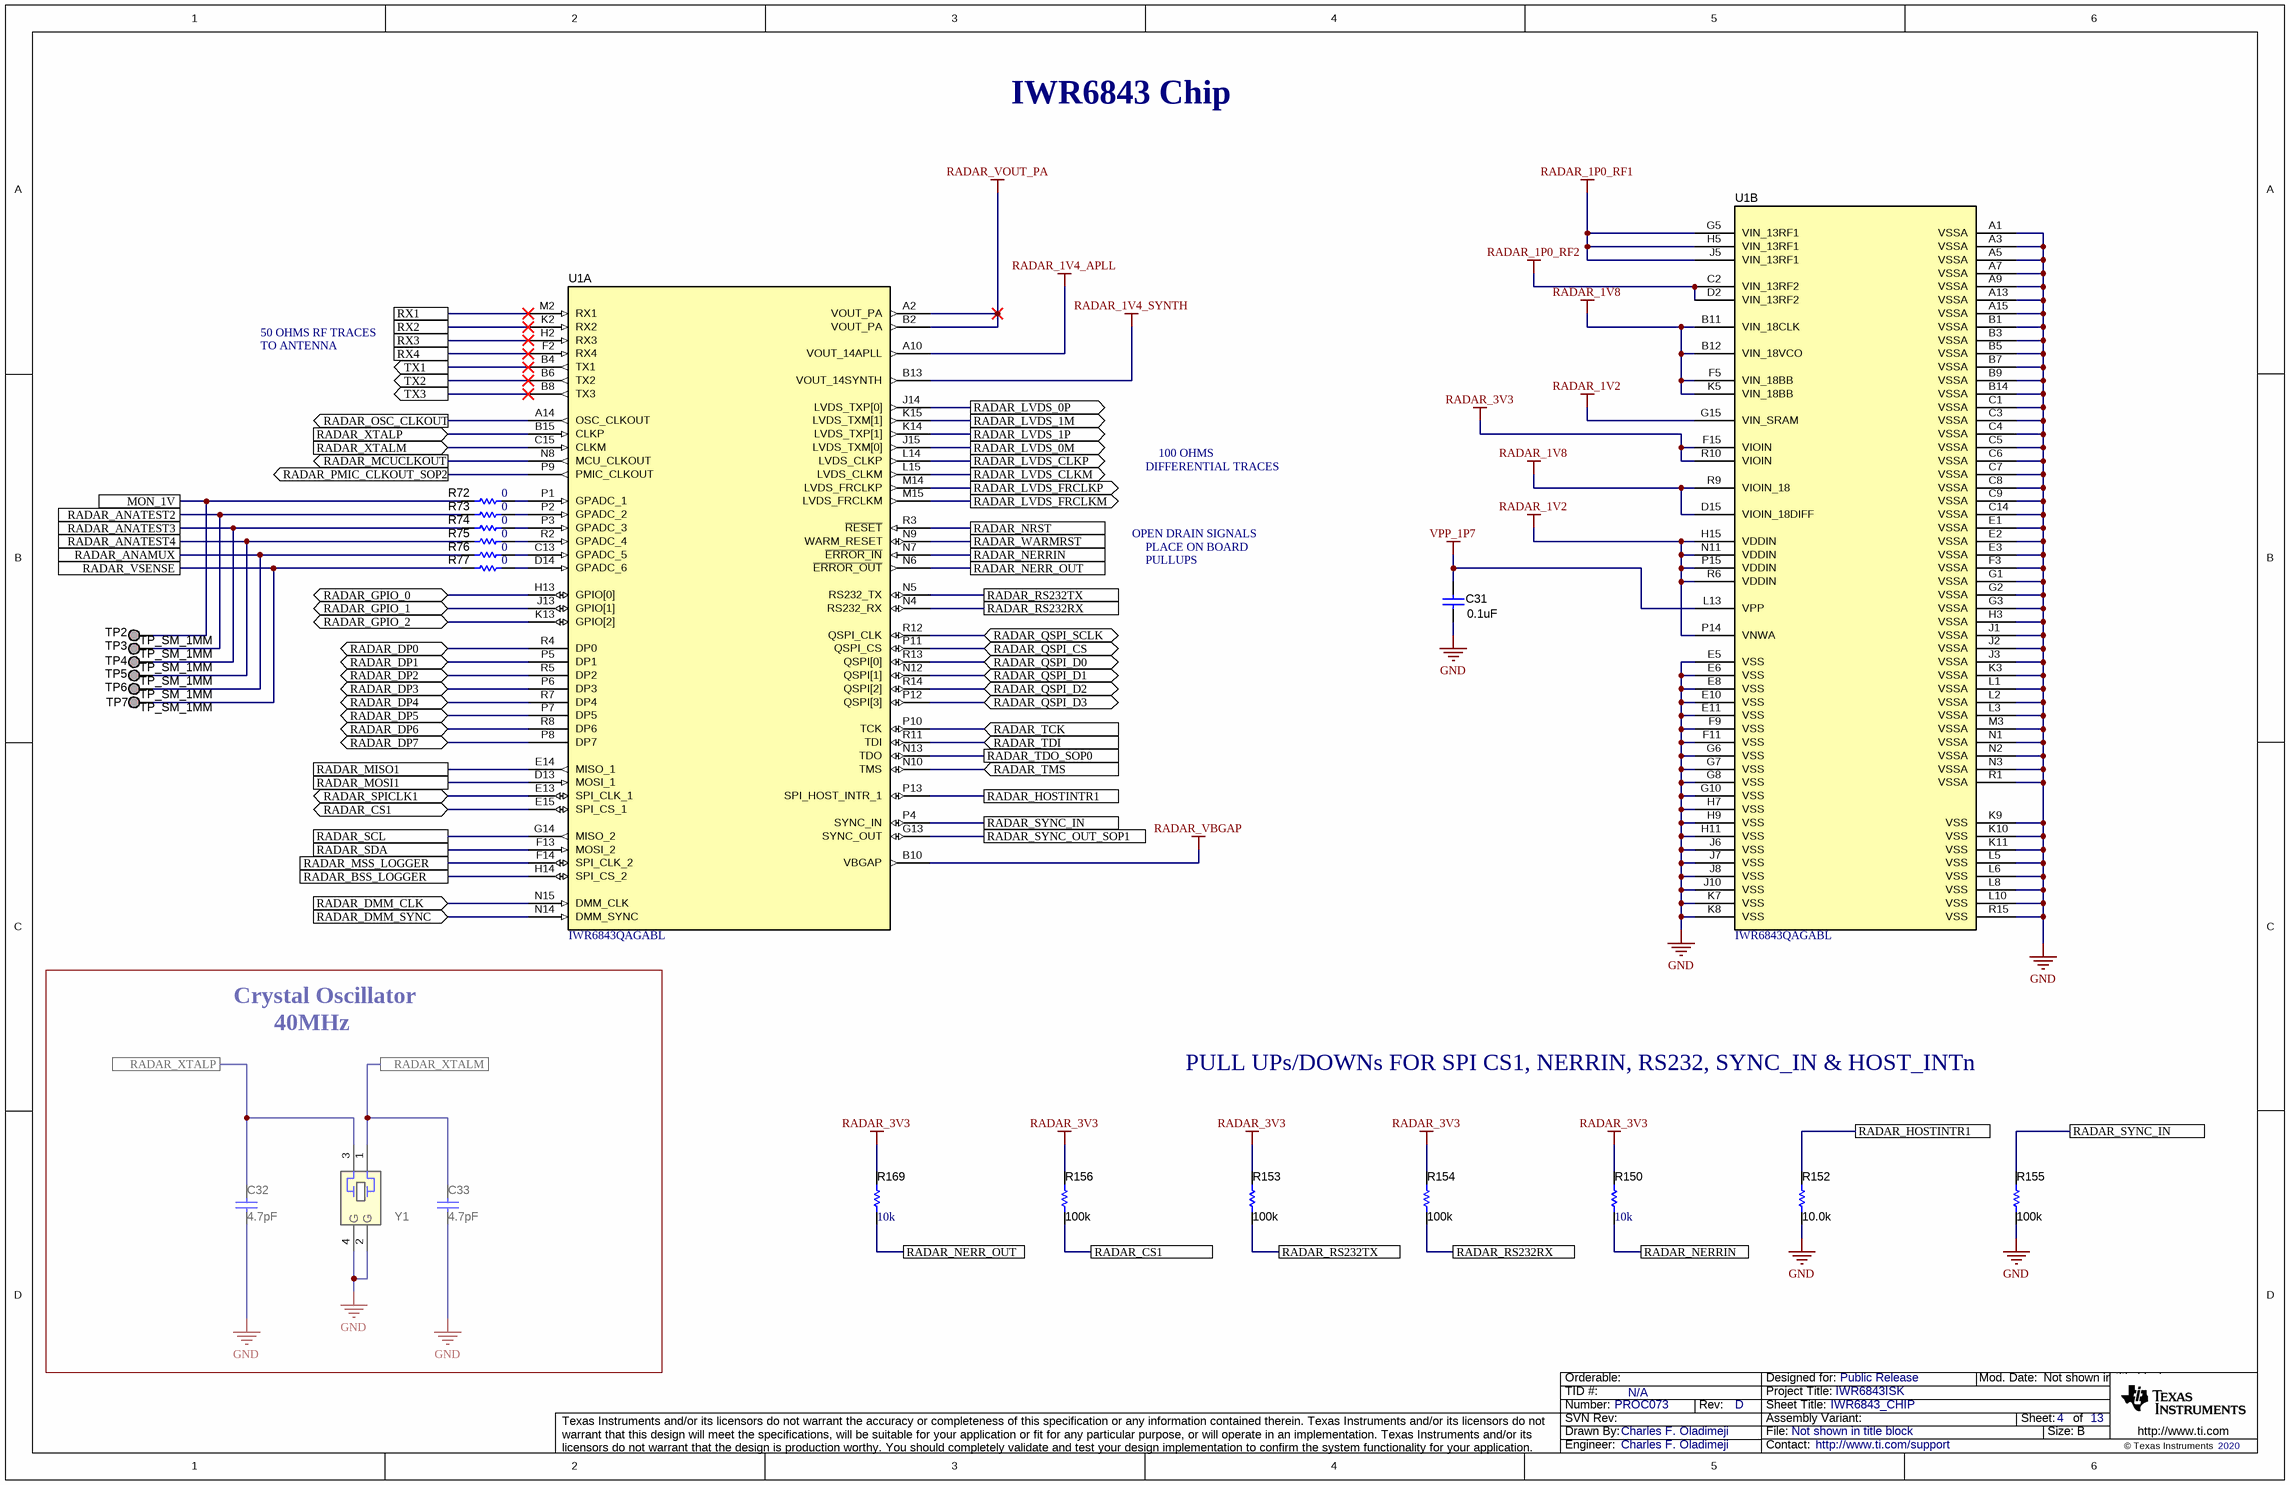
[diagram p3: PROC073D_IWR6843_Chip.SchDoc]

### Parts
C31  ValueDisplayed: 0.1uF  [0201]  (hidden comment: GRM033C71A104KE14D)
C32  ValueDisplayed: 4.7pF  [0402L]  (hidden comment: GJM1555C1H4R7BB01D)
C33  ValueDisplayed: 4.7pF  [0402L]  (hidden comment: GJM1555C1H4R7BB01D)
R72  ValueDisplayed: 0  [0402]  (hidden comment: ERJ-2GE0R00X)
R73  ValueDisplayed: 0  [0402]  (hidden comment: ERJ-2GE0R00X)
R74  ValueDisplayed: 0  [0402]  (hidden comment: ERJ-2GE0R00X)
R75  ValueDisplayed: 0  [0402]  (hidden comment: ERJ-2GE0R00X)
R76  ValueDisplayed: 0  [0402]  (hidden comment: ERJ-2GE0R00X)
R77  ValueDisplayed: 0  [0402]  (hidden comment: ERJ-2GE0R00X)
R150  value 10k  [0402]  (hidden comment: CRCW040210K0JNED)
R152  ValueDisplayed: 10.0k  [0402L]  (hidden comment: CRCW040210K0FKED)
R153  ValueDisplayed: 100k  [0402L]  (hidden comment: CRCW0402100KFKED)
R154  ValueDisplayed: 100k  [0402L]  (hidden comment: CRCW0402100KFKED)
R155  ValueDisplayed: 100k  [0402L]  (hidden comment: CRCW0402100KFKED)
R156  ValueDisplayed: 100k  [0402L]  (hidden comment: CRCW0402100KFKED)
R169  value 10k  [0402]  (hidden comment: CRCW040210K0JNED)
TP2  TP_SM_1MM  [TP_SM_1MM]  (no BOM)
TP3  TP_SM_1MM  [TP_SM_1MM]  (no BOM)
TP4  TP_SM_1MM  [TP_SM_1MM]  (no BOM)
TP5  TP_SM_1MM  [TP_SM_1MM]  (no BOM)
TP6  TP_SM_1MM  [TP_SM_1MM]  (no BOM)
TP7  TP_SM_1MM  [TP_SM_1MM]  (no BOM)
U1  IWR6843QAGABL  [ABL0161B]  (parts A,B of 2)
Y1  CX3225SA40000D0PTWCC  [Kyocera_CX3225SA]  (value not drawn)

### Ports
MON_1V, RADAR_ANAMUX, RADAR_ANATEST2, RADAR_ANATEST3, RADAR_ANATEST4, RADAR_BSS_LOGGER, RADAR_CS1, RADAR_CS1 (bidir), RADAR_DMM_CLK (in), RADAR_DMM_SYNC (in), RADAR_DP0 (bidir), RADAR_DP1 (bidir), RADAR_DP2 (bidir), RADAR_DP3 (bidir), RADAR_DP4 (bidir), RADAR_DP5 (bidir), RADAR_DP6 (bidir), RADAR_DP7 (bidir), RADAR_GPIO_0 (bidir), RADAR_GPIO_1 (bidir), RADAR_GPIO_2 (bidir), RADAR_HOSTINTR1, RADAR_LVDS_0M (out), RADAR_LVDS_0P (out), RADAR_LVDS_1M (out), RADAR_LVDS_1P (out), RADAR_LVDS_CLKM (out), RADAR_LVDS_CLKP (out), RADAR_LVDS_FRCLKM (out), RADAR_LVDS_FRCLKP (out), RADAR_MCUCLKOUT (out), RADAR_MISO1, RADAR_MOSI1, RADAR_MSS_LOGGER, RADAR_NERR_OUT, RADAR_NERRIN, RADAR_NRST, RADAR_OSC_CLKOUT (out), RADAR_PMIC_CLKOUT_SOP2 (out), RADAR_QSPI_CS (bidir), RADAR_QSPI_D0 (bidir), RADAR_QSPI_D1 (bidir), RADAR_QSPI_D2 (bidir), RADAR_QSPI_D3 (bidir), RADAR_QSPI_SCLK (bidir), RADAR_RS232RX, RADAR_RS232TX, RADAR_SCL, RADAR_SDA, RADAR_SPICLK1 (bidir), RADAR_SYNC_IN, RADAR_SYNC_OUT_SOP1, RADAR_TCK (in), RADAR_TDI (in), RADAR_TDO_SOP0, RADAR_TMS (in), RADAR_VSENSE, RADAR_WARMRST, RADAR_XTALM, RADAR_XTALM (in), RADAR_XTALP, RADAR_XTALP (in), RX1, RX2, RX3, RX4, TX1 (out), TX2 (out), TX3 (out)

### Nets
GND: C31.1 C32.1 C33.1 R152.1 R155.1 U1.A1(VSSA) U1.A3(VSSA) U1.A5(VSSA) U1.A7(VSSA) U1.A9(VSSA) U1.A13(VSSA) U1.A15(VSSA) U1.B1(VSSA) U1.B3(VSSA) U1.B5(VSSA) U1.B7(VSSA) U1.B9(VSSA) U1.B14(VSSA) U1.C1(VSSA) U1.C3(VSSA) U1.C4(VSSA) U1.C5(VSSA) U1.C6(VSSA) U1.C7(VSSA) U1.C8(VSSA) U1.C9(VSSA) U1.C14(VSSA) U1.E1(VSSA) U1.E2(VSSA) U1.E3(VSSA) U1.E5(VSS) U1.E6(VSS) U1.E8(VSS) U1.E10(VSS) U1.E11(VSS) U1.F3(VSSA) U1.F9(VSS) U1.F11(VSS) U1.G1(VSSA) U1.G2(VSSA) U1.G3(VSSA) U1.G6(VSS) U1.G7(VSS) U1.G8(VSS) U1.G10(VSS) U1.H3(VSSA) U1.H7(VSS) U1.H9(VSS) U1.H11(VSS) U1.J1(VSSA) U1.J2(VSSA) U1.J3(VSSA) U1.J6(VSS) U1.J7(VSS) U1.J8(VSS) U1.J10(VSS) U1.K3(VSSA) U1.K7(VSS) U1.K8(VSS) U1.K9(VSS) U1.K10(VSS) U1.K11(VSS) U1.L1(VSSA) U1.L2(VSSA) U1.L3(VSSA) U1.L5(VSS) U1.L6(VSS) U1.L8(VSS) U1.L10(VSS) U1.M3(VSSA) U1.N1(VSSA) U1.N2(VSSA) U1.N3(VSSA) U1.R1(VSSA) U1.R15(VSS) Y1.2(GND) Y1.4(GND)
RADAR_1P0_RF1: U1.G5(VIN_13RF1) U1.H5(VIN_13RF1) U1.J5(VIN_13RF1)
RADAR_1P0_RF2: U1.C2(VIN_13RF2) U1.D2(VIN_13RF2)
RADAR_1V2: U1.G15(VIN_SRAM) U1.H15(VDDIN) U1.N11(VDDIN) U1.P14(VNWA) U1.P15(VDDIN) U1.R6(VDDIN)
RADAR_1V4_APLL: U1.A10(VOUT_14APLL)
RADAR_1V4_SYNTH: U1.B13(VOUT_14SYNTH)
RADAR_1V8: U1.B11(VIN_18CLK) U1.B12(VIN_18VCO) U1.D15(VIOIN_18DIFF) U1.F5(VIN_18BB) U1.K5(VIN_18BB) U1.R9(VIOIN_18)
RADAR_3V3: R150.2 R153.2 R154.2 R156.2 R169.2 U1.F15(VIOIN) U1.R10(VIOIN)
RADAR_VBGAP: U1.B10(VBGAP)
RADAR_VOUT_PA: U1.A2(VOUT_PA) U1.B2(VOUT_PA)
VPP_1P7: C31.2 U1.L13(VPP)
MON_1V: R72.1 TP2.1 ; port MON_1V
RADAR_ANAMUX: R76.1 TP6.1 ; port RADAR_ANAMUX
RADAR_ANATEST2: R73.1 TP3.1 ; port RADAR_ANATEST2
RADAR_ANATEST3: R74.1 TP4.1 ; port RADAR_ANATEST3
RADAR_ANATEST4: R75.1 TP5.1 ; port RADAR_ANATEST4
RADAR_BSS_LOGGER: U1.H14(SPI_CS_2) ; port RADAR_BSS_LOGGER
RADAR_CS1: R156.1 U1.E15(SPI_CS_1) ; port RADAR_CS1
RADAR_DMM_CLK: U1.N15(DMM_CLK) ; port RADAR_DMM_CLK
RADAR_DMM_SYNC: U1.N14(DMM_SYNC) ; port RADAR_DMM_SYNC
RADAR_DP0: U1.R4(DP0) ; port RADAR_DP0
RADAR_DP1: U1.P5(DP1) ; port RADAR_DP1
RADAR_DP2: U1.R5(DP2) ; port RADAR_DP2
RADAR_DP3: U1.P6(DP3) ; port RADAR_DP3
RADAR_DP4: U1.R7(DP4) ; port RADAR_DP4
RADAR_DP5: U1.P7(DP5) ; port RADAR_DP5
RADAR_DP6: U1.R8(DP6) ; port RADAR_DP6
RADAR_DP7: U1.P8(DP7) ; port RADAR_DP7
RADAR_GPIO_0: U1.H13(GPIO[0]) ; port RADAR_GPIO_0
RADAR_GPIO_1: U1.J13(GPIO[1]) ; port RADAR_GPIO_1
RADAR_GPIO_2: U1.K13(GPIO[2]) ; port RADAR_GPIO_2
RADAR_HOSTINTR1: R152.2 U1.P13(SPI_HOST_INTR_1) ; port RADAR_HOSTINTR1
RADAR_LVDS_0M: U1.J15(LVDS_TXM[0]) ; port RADAR_LVDS_0M
RADAR_LVDS_0P: U1.J14(LVDS_TXP[0]) ; port RADAR_LVDS_0P
RADAR_LVDS_1M: U1.K15(LVDS_TXM[1]) ; port RADAR_LVDS_1M
RADAR_LVDS_1P: U1.K14(LVDS_TXP[1]) ; port RADAR_LVDS_1P
RADAR_LVDS_CLKM: U1.L15(LVDS_CLKM) ; port RADAR_LVDS_CLKM
RADAR_LVDS_CLKP: U1.L14(LVDS_CLKP) ; port RADAR_LVDS_CLKP
RADAR_LVDS_FRCLKM: U1.M15(LVDS_FRCLKM) ; port RADAR_LVDS_FRCLKM
RADAR_LVDS_FRCLKP: U1.M14(LVDS_FRCLKP) ; port RADAR_LVDS_FRCLKP
RADAR_MCUCLKOUT: U1.N8(MCU_CLKOUT) ; port RADAR_MCUCLKOUT
RADAR_MISO1: U1.E14(MISO_1) ; port RADAR_MISO1
RADAR_MOSI1: U1.D13(MOSI_1) ; port RADAR_MOSI1
RADAR_MSS_LOGGER: U1.F14(SPI_CLK_2) ; port RADAR_MSS_LOGGER
RADAR_NERR_OUT: R169.1 U1.N6(~{ERROR_OUT}) ; port RADAR_NERR_OUT
RADAR_NERRIN: R150.1 U1.N7(~{ERROR_IN}) ; port RADAR_NERRIN
RADAR_NRST: U1.R3(~{RESET}) ; port RADAR_NRST
RADAR_OSC_CLKOUT: U1.A14(OSC_CLKOUT) ; port RADAR_OSC_CLKOUT
RADAR_PMIC_CLKOUT_SOP2: U1.P9(PMIC_CLKOUT) ; port RADAR_PMIC_CLKOUT_SOP2
RADAR_QSPI_CS: U1.P11(QSPI_CS) ; port RADAR_QSPI_CS
RADAR_QSPI_D0: U1.R13(QSPI[0]) ; port RADAR_QSPI_D0
RADAR_QSPI_D1: U1.N12(QSPI[1]) ; port RADAR_QSPI_D1
RADAR_QSPI_D2: U1.R14(QSPI[2]) ; port RADAR_QSPI_D2
RADAR_QSPI_D3: U1.P12(QSPI[3]) ; port RADAR_QSPI_D3
RADAR_QSPI_SCLK: U1.R12(QSPI_CLK) ; port RADAR_QSPI_SCLK
RADAR_RS232RX: R154.1 U1.N4(RS232_RX) ; port RADAR_RS232RX
RADAR_RS232TX: R153.1 U1.N5(RS232_TX) ; port RADAR_RS232TX
RADAR_SCL: U1.G14(MISO_2) ; port RADAR_SCL
RADAR_SDA: U1.F13(MOSI_2) ; port RADAR_SDA
RADAR_SPICLK1: U1.E13(SPI_CLK_1) ; port RADAR_SPICLK1
RADAR_SYNC_IN: R155.2 U1.P4(SYNC_IN) ; port RADAR_SYNC_IN
RADAR_SYNC_OUT_SOP1: U1.G13(SYNC_OUT) ; port RADAR_SYNC_OUT_SOP1
RADAR_TCK: U1.P10(TCK) ; port RADAR_TCK
RADAR_TDI: U1.R11(TDI) ; port RADAR_TDI
RADAR_TDO_SOP0: U1.N13(TDO) ; port RADAR_TDO_SOP0
RADAR_TMS: U1.N10(TMS) ; port RADAR_TMS
RADAR_VSENSE: R77.1 TP7.1 ; port RADAR_VSENSE
RADAR_WARMRST: U1.N9(WARM_RESET) ; port RADAR_WARMRST
RADAR_XTALM: C33.2 U1.C15(CLKM) Y1.1 ; port RADAR_XTALM
RADAR_XTALP: C32.2 U1.B15(CLKP) Y1.3 ; port RADAR_XTALP
RX1: U1.M2(RX1) ; port RX1
RX2: U1.K2(RX2) ; port RX2
RX3: U1.H2(RX3) ; port RX3
RX4: U1.F2(RX4) ; port RX4
TX1: U1.B4(TX1) ; port TX1
TX2: U1.B6(TX2) ; port TX2
TX3: U1.B8(TX3) ; port TX3
NetR72_2: R72.2 U1.P1(GPADC_1)
NetR73_2: R73.2 U1.P2(GPADC_2)
NetR74_2: R74.2 U1.P3(GPADC_3)
NetR75_2: R75.2 U1.R2(GPADC_4)
NetR76_2: R76.2 U1.C13(GPADC_5)
NetR77_2: R77.2 U1.D14(GPADC_6)

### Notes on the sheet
- IWR6843 Chip
- 50 OHMS RF TRACES
- TO ANTENNA
- DIFFERENTIAL TRACES
- 100 OHMS
- OPEN DRAIN SIGNALS
- PLACE ON BOARD
- PULLUPS
- Crystal Oscillator
- 40MHz
- PULL UPs/DOWNs FOR SPI CS1, NERRIN, RS232, SYNC_IN & HOST_INTn

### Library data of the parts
C31 = CMP-0064969-1: CAP, CERM, 0.1 uF, 10 V,+/- 10%, X7S, 0201; Manufacturer: MuRata; TaMin_C: -55°C; Polarized: N; SizeAreaWB_mm2: 2.08; Value1: Unknown; U/M: EA; Value: 0.1uF; TaMax_C: 125°C; SizeZ_mm: 0.26; SizeX_mm: 0.6; SizeY_mm: 0.3; Value2: 10V; SizeArea_mm2: 0.18; Cap_F: 100nF; AEC Category: Q200
C32 C33 = CMP-0006367-2: CAP, CERM, 4.7 pF, 50 V, +/- 2%, C0G/NP0, 0402; Manufacturer: MuRata; TaMin_C: -55°C; Polarized: N; SizeAreaWB_mm2: 3; Value1: Unknown; U/M: EA; Value: 4.7pF; TaMax_C: 125°C; SizeZ_mm: 0.6; SizeX_mm: 1; SizeY_mm: 0.5; Cap_Case: 0402; Value2: 50V; CompType: Capacitor; AEC Category: Q200
R72-R77 = CMP-0026992-3: RES, 0, 5%, 0.1 W, AEC-Q200 Grade 0, 0402; Manufacturer: Panasonic; Power_W: 100mW; TempCo: 600 ppm/C; Value_Code: 0000; Value: 0; EIA_Code: E24; SizeX_mm: 1; SizeY_mm: 0.5; SizeZ_mm: 0.6; Value2: 0.1W; AEC Qualified: Y; VDC_V: 50V; AEC Category: Q200; SizeAreaWB_mm2: 3
R150 R169 = CMP-0026825-5: RES, 10 k, 5%, 0.063 W, AEC-Q200 Grade 0, 0402; Manufacturer: Vishay-Dale; Power_W: 63mW; TempCo: 200 ppm/C; Value_Code: 10k0; EIA_Code: E24; SizeX_mm: 1; SizeY_mm: 0.5; SizeZ_mm: 0.6; Value2: 0.063W; CompType: Resistor; AEC Qualified: Y; VDC_V: 50V; AEC Category: Q200; AEC Grade: 0; INSTALLATION: DNP
R152 = CMP-0025958-3: RES, 10.0 k, 1%, 0.063 W, AEC-Q200 Grade 0, 0402; Manufacturer: Vishay-Dale; Power_W: 63mW; TempCo: 100 ppm/C; Value_Code: 10k0; Value: 10.0k; EIA_Code: E96; Res_ohm: 10k; SizeX_mm: 1; SizeY_mm: 0.5; SizeZ_mm: 0.6; Value2: 0.063W; AEC Qualified: Y; VDC_V: 50V; AEC Category: Q200; AEC Grade: 0
R153-R156 = CMP-0025950-3: as R182 on sheet PROC073D_PMIC
TP2-TP7 = CMP-0003825-1: 1mm Test Point, SMT; Manufacturer: Any
U1 = CMP-0081105-1: IWR1843QAGABL, ABL0161B (FCBGA-161); Alternate Manufacturer: Texas Instruments; SizeAreaWB_mm2: 153.76; SizeZ_mm: 1.17; SizeX_mm: 10.4; SizeArea_mm2: 108.16; CompType: IC; AEC Qualified: N; AEC Category: Q200
Y1 = CMP-0004694-3: Crystal, 40 MHz, 8pF, SMD; Manufacturer: Kyocera; TaMin_C: -40°C; Frequency Stability: +/-200ppm; SizeAreaWB_mm2: 14.7; Frequency_Fixed: 40MHz; TaMax_C: 125°C; SizeZ_mm: 0.8; SizeX_mm: 2.5; SizeY_mm: 3.2; SizeArea_mm2: 8

## Sheet PROC073D_Decoupling_caps.SchDoc: Decoupling Caps
size 431 x 279 mm; Date: Not shown in title block; ApprovedBy: Not shown in title block; CheckedBy: Not shown in title block; Author: Not shown in title block; CompanyName: Not shown in title block; DrawnBy: Charles F. Oladimeji; Engineer: Not shown in title block; Organization: Not shown in title block; Address1: Not shown in title block; Address2: Not shown in title block; Address3: Not shown in title block; Address4: Not shown in title block; DocumentNumber: 5; Revision: Use project parameter SCH_Rev; SheetNumber: 5; SheetTotal: 13; PageSetup: Record=PageOptions¦CenterHorizontal=True¦CenterVertical=True¦PrintScale=1.00¦XCorrection=1.00¦YCorrection=1.00¦PrintKind=0¦BorderSize=5000000¦LeftOffset=0¦BottomOffset=0¦Orientation=2¦PaperLength=1000¦PaperWidth=1000¦Scale=100¦PaperSource=15¦PrintQuality=600¦MediaType=1¦DitherType=10¦PaperKind=Letter¦PrintScaleMode=1
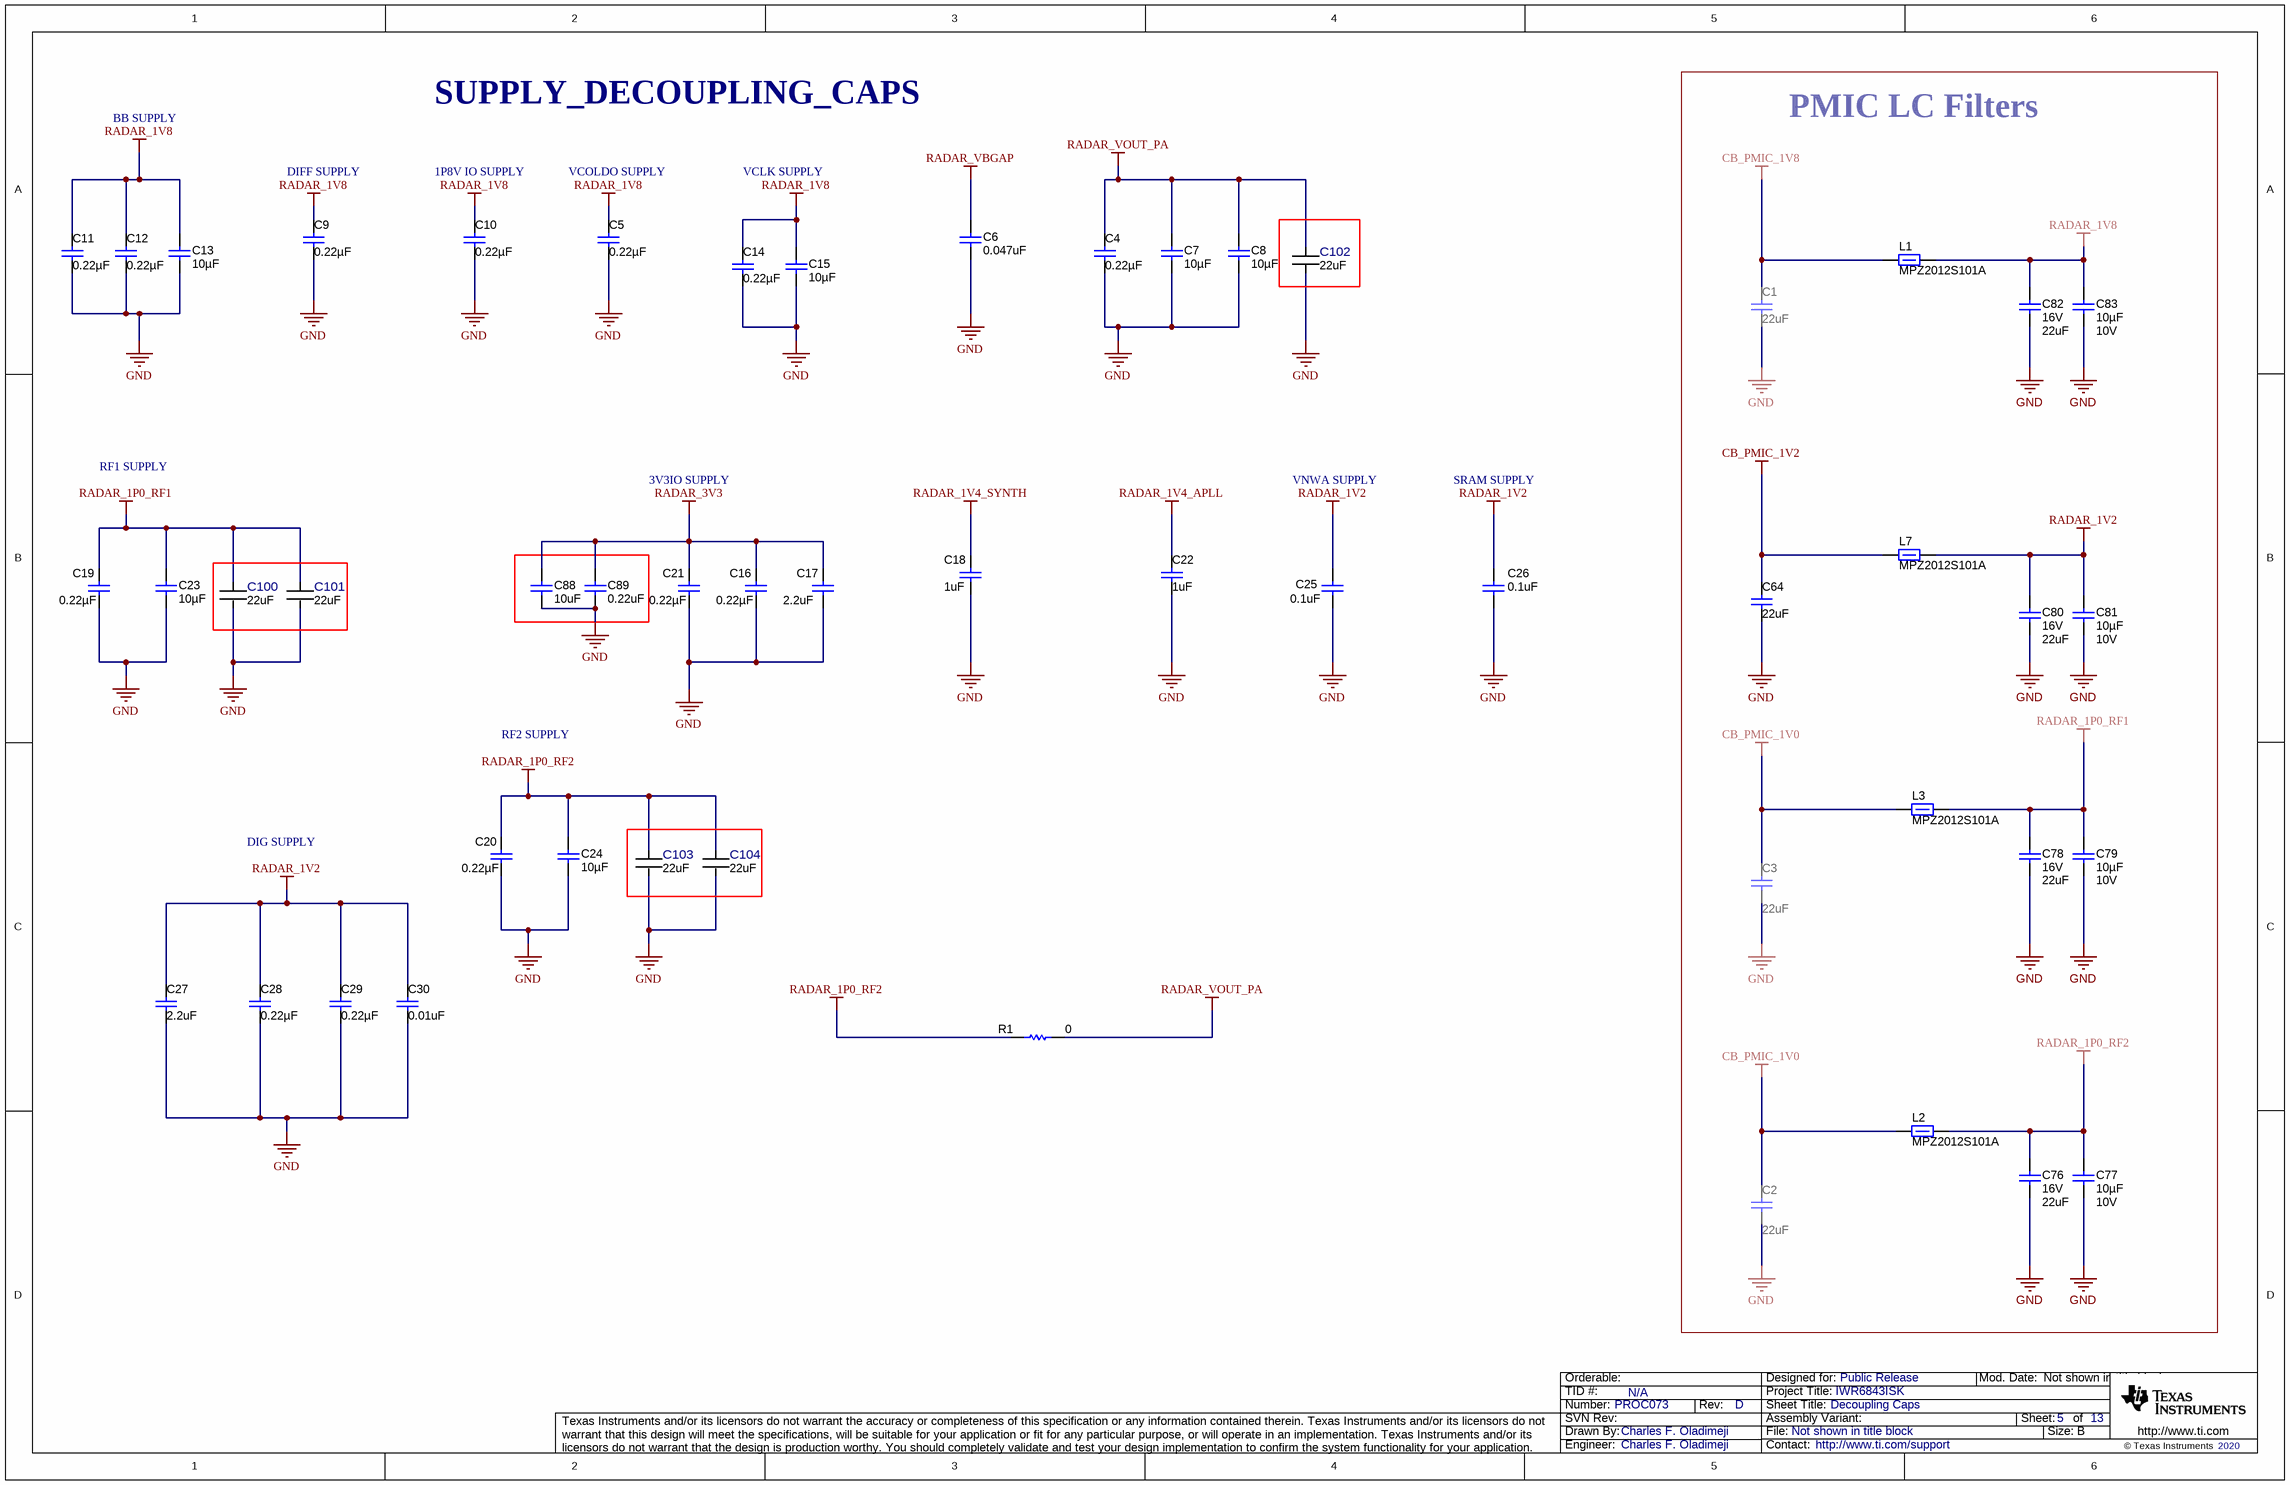
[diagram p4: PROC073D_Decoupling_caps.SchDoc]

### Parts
C1  ValueDisplayed: 22uF  [1206_180]  (hidden comment: CGA5L1X7R0J226M160AC)
C2  ValueDisplayed: 22uF  [1206_180]  (hidden comment: CGA5L1X7R0J226M160AC)
C3  ValueDisplayed: 22uF  [1206_180]  (hidden comment: CGA5L1X7R0J226M160AC)
C4  ValueDisplayed: 0.22µF  [0402L]  (hidden comment: GCM155R71C224KE02D)
C5  ValueDisplayed: 0.22µF  [0402L]  (hidden comment: GCM155R71C224KE02D)
C6  ValueDisplayed: 0.047uF  [0402L]  (hidden comment: CGA2B3X7R1H473K050BB)
C7  Cap_F: 10µF  [0805_HV]  (hidden comment: C0805C106M8RACTU)
C8  Cap_F: 10µF  [0805_HV]  (hidden comment: C0805C106M8RACTU)
C9  ValueDisplayed: 0.22µF  [0402L]  (hidden comment: GCM155R71C224KE02D)
C10  ValueDisplayed: 0.22µF  [0402L]  (hidden comment: GCM155R71C224KE02D)
C11  ValueDisplayed: 0.22µF  [0402L]  (hidden comment: GCM155R71C224KE02D)
C12  ValueDisplayed: 0.22µF  [0402L]  (hidden comment: GCM155R71C224KE02D)
C13  Cap_F: 10µF  [0805_HV]  (hidden comment: C0805C106M8RACTU)
C14  ValueDisplayed: 0.22µF  [0402L]  (hidden comment: GCM155R71C224KE02D)
C15  Cap_F: 10µF  [0805_HV]  (hidden comment: C0805C106M8RACTU)
C16  ValueDisplayed: 0.22µF  [0402L]  (hidden comment: GCM155R71C224KE02D)
C17  ValueDisplayed: 2.2uF  [0603]  (hidden comment: GCM188R70J225KE22D)
C18  ValueDisplayed: 1uF  [0603]  (hidden comment: GCM188R71C105KA64D)
C19  ValueDisplayed: 0.22µF  [0402L]  (hidden comment: GCM155R71C224KE02D)
C20  ValueDisplayed: 0.22µF  [0402L]  (hidden comment: GCM155R71C224KE02D)
C21  ValueDisplayed: 0.22µF  [0402L]  (hidden comment: GCM155R71C224KE02D)
C22  ValueDisplayed: 1uF  [0603]  (hidden comment: GCM188R71C105KA64D)
C23  Cap_F: 10µF  [0805_HV]  (hidden comment: C0805C106M8RACTU)
C24  Cap_F: 10µF  [0805_HV]  (hidden comment: C0805C106M8RACTU)
C25  ValueDisplayed: 0.1uF  [0402L]  (hidden comment: GCM155R71C104KA55D)
C26  ValueDisplayed: 0.1uF  [0402L]  (hidden comment: GCM155R71C104KA55D)
C27  ValueDisplayed: 2.2uF  [0603]  (hidden comment: GCM188R70J225KE22D)
C28  ValueDisplayed: 0.22µF  [0402L]  (hidden comment: GCM155R71C224KE02D)
C29  ValueDisplayed: 0.22µF  [0402L]  (hidden comment: GCM155R71C224KE02D)
C30  ValueDisplayed: 0.01uF  [0402L]  (hidden comment: GCM155R71E103KA37D)
C64  ValueDisplayed: 22uF  [1206_180]  (hidden comment: CGA5L1X7R0J226M160AC)
C76  VDC_V: 16V  ValueDisplayed: 22uF  [1210_280]  (hidden comment: GCM32ER71C226KE19L)
C77  Cap_F: 10µF  VDC_V: 10V  [0805_HV]  (hidden comment: GCM21BR71A106KE22L)
C78  VDC_V: 16V  ValueDisplayed: 22uF  [1210_280]  (hidden comment: GCM32ER71C226KE19L)
C79  Cap_F: 10µF  VDC_V: 10V  [0805_HV]  (hidden comment: GCM21BR71A106KE22L)
C80  VDC_V: 16V  ValueDisplayed: 22uF  [1210_280]  (hidden comment: GCM32ER71C226KE19L)
C81  Cap_F: 10µF  VDC_V: 10V  [0805_HV]  (hidden comment: GCM21BR71A106KE22L)
C82  VDC_V: 16V  ValueDisplayed: 22uF  [1210_280]  (hidden comment: GCM32ER71C226KE19L)
C83  Cap_F: 10µF  VDC_V: 10V  [0805_HV]  (hidden comment: GCM21BR71A106KE22L)
C88  ValueDisplayed: 10uF  [0603S]  (hidden comment: GRT188R61A106KE13D)
C89  ValueDisplayed: 0.22uF  [0402S]  (hidden comment: LMK105B7224KVHF)
C100  Cap_F: 22uF  [FP-CL05A226MQ5N6J8_0402 (1005 Metric)-IPC_C]  (hidden comment: CL05A226MQ5N6J8)
C101  Cap_F: 22uF  [FP-CL05A226MQ5N6J8_0402 (1005 Metric)-IPC_C]  (hidden comment: CL05A226MQ5N6J8)
C102  Cap_F: 22uF  [FP-CL05A226MQ5N6J8_0402 (1005 Metric)-IPC_C]  (hidden comment: CL05A226MQ5N6J8)
C103  Cap_F: 22uF  [FP-CL05A226MQ5N6J8_0402 (1005 Metric)-IPC_C]  (hidden comment: CL05A226MQ5N6J8)
C104  Cap_F: 22uF  [FP-CL05A226MQ5N6J8_0402 (1005 Metric)-IPC_C]  (hidden comment: CL05A226MQ5N6J8)
L1  MPZ2012S101A  [MPZ2012]
L2  MPZ2012S101A  [MPZ2012]
L3  MPZ2012S101A  [MPZ2012]
L7  MPZ2012S101A  [MPZ2012]
R1  ValueDisplayed: 0  [0603]  (hidden comment: MCT06030Z0000ZP500)

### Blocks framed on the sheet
PMIC LC Filters: C1-C3 C64 C76-C83 L1-L3 L7

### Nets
CB_PMIC_1V0: C2.2 C3.2 L2.1 L3.1
CB_PMIC_1V2: C64.2 L7.1
CB_PMIC_1V8: C1.2 L1.1
GND: C1.1 C2.1 C3.1 C4.1 C5.1 C6.2 C7.1 C8.1 C9.1 C10.1 C11.1 C12.1 C13.1 C14.1 C15.1 C16.1 C17.1 C18.1 C19.1 C20.1 C21.1 C22.1 C23.1 C24.1 C25.1 C26.1 C27.1 C28.1 C29.1 C30.2 C64.1 C76.2 C77.2 C78.2 C79.2 C80.2 C81.2 C82.2 C83.2 C88.1 C89.2 C100.2 C101.2 C102.2 C103.2 C104.2
RADAR_1P0_RF1: C19.2 C23.2 C78.1 C79.1 C100.1 C101.1 L3.2
RADAR_1P0_RF2: C20.2 C24.2 C76.1 C77.1 C103.1 C104.1 L2.2 R1.1
RADAR_1V2: C25.2 C26.2 C27.2 C28.2 C29.2 C30.1 C80.1 C81.1 L7.2
RADAR_1V4_APLL: C22.2
RADAR_1V4_SYNTH: C18.2
RADAR_1V8: C5.2 C9.2 C10.2 C11.2 C12.2 C13.2 C14.2 C15.2 C82.1 C83.1 L1.2
RADAR_3V3: C16.2 C17.2 C21.2 C88.2 C89.1
RADAR_VBGAP: C6.1
RADAR_VOUT_PA: C4.2 C7.2 C8.2 C102.1 R1.2

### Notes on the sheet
- BB SUPPLY
- SUPPLY_DECOUPLING_CAPS
- DIFF SUPPLY
- 1P8V IO SUPPLY
- VCOLDO SUPPLY
- VCLK SUPPLY
- RF1 SUPPLY
- 3V3IO SUPPLY
- VNWA SUPPLY
- SRAM SUPPLY
- RF2 SUPPLY
- DIG SUPPLY

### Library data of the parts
C1-C3 C64 = CMP-0008770-2: CAP, CERM, 22 uF, 6.3 V, +/- 10%, X7R, AEC-Q200 Grade 1, 1206; Manufacturer: TDK; TaMin_C: -55°C; ESR_ohm: 1.872m; Polarized: N; SizeAreaWB_mm2: 10.92; Value1: 0.001872 ohm; U/M: EA; Value: 22uF; SizeZ_mm: 1.8; SizeX_mm: 3.2; SizeY_mm: 1.6; Value2: 6.3V; SizeArea_mm2: 5.12; CompType: Capacitor; AEC Qualified: Y; Cap_F: 22µF; IRMS_A: 5.30203A; AEC Grade: 1; AEC Category: Q200; TaMax_C: 125°C; INSTALLATION: DNP
C4 C5 C9-C12 C14 C16 C19-C21 C28 C29 = CMP-0078265-1: CAP, CERM, 0.22 µF, 16 V,+/- 10%, X7R, AEC-Q200 Grade 1, 0402; Manufacturer: MuRata; TaMin_C: -55°C; Polarized: N; SizeAreaWB_mm2: 3; U/M: EA; Value: 0.22uF; TaMax_C: 125°C; SizeZ_mm: 0.6; SizeX_mm: 1; SizeY_mm: 0.5; Cap_Case: 0402; Value2: 16V; CompType: Capacitor; AEC Qualified: Y; Cap_F: 220nF; AEC Category: Q200
C6 = CMP-0006330-2: CAP, CERM, 0.047 uF, 50 V, +/- 10%, X7R, AEC-Q200 Grade 1, 0402; Manufacturer: TDK; Polarized: N; U/M: EA; Cap_F: 47nF; ESR_ohm: 0.06407; Value1: 0.06407 ohm; VDC_V: 50V; IRMS_A: 646.122mA; TaMin_C: -55°C; TaMax_C: 125°C; Cap_Case: 0402; SizeArea_mm2: 0.5; SizeAreaWB_mm2: 3; SizeX_mm: 1; SizeZ_mm: 0.6; AEC Category: Q200; AEC Qualified: Y
C7 C8 C13 C15 C23 C24 = CMP-0085348-1: CAP, CERM, 10 µF, 10 V,+/- 20%, X7R, 0805; Manufacturer: Kemet; TaMin_C: -55°C; SizeZ_mm: 1.45; U/M: EA; SizeY_mm: 1.25; Value2: 10V; SizeAreaWB_mm2: 6.75; SizeArea_mm2: 2.5; Value: 10uF; AEC Qualified: N; TaMax_C: 125°C; SizeX_mm: 2; Cap_Case: 0805; AEC Category: Q200
C17 C27 = CMP-0007134-5: CAP, CERM, 2.2 uF, 6.3 V, +/- 10%, X7R, AEC-Q200 Grade 1, 0603; Manufacturer: MuRata; TaMin_C: -55°C; Polarized: N; SizeAreaWB_mm2: 4.68; Value1: Unknown; U/M: EA; Value: 2.2uF; TaMax_C: 125°C; SizeZ_mm: 1; SizeX_mm: 1.6; SizeY_mm: 0.8; Value2: 6.3V; SizeArea_mm2: 1.28; CompType: Capacitor; AEC Qualified: Y; Cap_F: 2.2µF; AEC Category: Q200
C18 C22 = CMP-0007136-5: CAP, CERM, 1 uF, 16 V, +/- 10%, X7R, AEC-Q200 Grade 1, 0603; Manufacturer: MuRata; TaMin_C: -55°C; Polarized: N; SizeAreaWB_mm2: 4.68; Value1: Unknown; U/M: EA; Value: 1uF; TaMax_C: 125°C; SizeZ_mm: 1; SizeX_mm: 1.6; SizeY_mm: 0.8; Value2: 16V; SizeArea_mm2: 1.28; CompType: Capacitor; AEC Qualified: Y; Cap_F: 1µF; AEC Category: Q200
C25 C26 = CMP-0006351-2: CAP, CERM, 0.1 uF, 16 V, +/- 10%, X7R, 0402; Manufacturer: MuRata; TaMin_C: -55°C; Polarized: N; SizeAreaWB_mm2: 3; Value1: Unknown; U/M: EA; Value: 0.1uF; TaMax_C: 125°C; SizeZ_mm: 0.6; SizeX_mm: 1; SizeY_mm: 0.5; Cap_Case: 0402; Value2: 16V; CompType: Capacitor; Cap_F: 100nF; AEC Category: Q200
C30 = CMP-0006352-2: CAP, CERM, 0.01 uF, 25 V, +/- 10%, X7R, 0402; Manufacturer: MuRata; TaMin_C: -55°C; Polarized: N; SizeAreaWB_mm2: 3; Value1: Unknown; U/M: EA; Value: 0.01uF; TaMax_C: 125°C; SizeZ_mm: 0.6; SizeX_mm: 1; SizeY_mm: 0.5; Cap_Case: 0402; Value2: 25V; CompType: Capacitor; Cap_F: 10nF; AEC Category: Q200
C76 C78 C80 C82 = CMP-0009174-2: CAP, CERM, 22 uF, 16 V, +/- 10%, X7R, 1210; Manufacturer: MuRata; TaMin_C: -55°C; Polarized: N; SizeAreaWB_mm2: 14.7; Value1: Unknown; U/M: EA; Value: 22uF; TaMax_C: 125°C; SizeZ_mm: 2.8; SizeX_mm: 3.2; SizeY_mm: 2.5; Cap_Case: 1210; SizeArea_mm2: 8; Cap_F: 22µF; AEC Category: Q200
C77 C79 C81 C83 = CMP-0008017-2: CAP, CERM, 10 uF, 10 V, +/- 10%, X7R, 0805; Manufacturer: MuRata; TaMin_C: -55°C; Polarized: N; SizeAreaWB_mm2: 6.75; Value1: Unknown; U/M: EA; Value: 10uF; TaMax_C: 125°C; SizeZ_mm: 1.45; SizeX_mm: 2; SizeY_mm: 1.25; Cap_Case: 0805; SizeArea_mm2: 2.5; AEC Category: Q200
C88 = CMP-0007497-5: as C87 on sheet PROC073D_PMIC
C89 = CMP-0006262-2: CAP, CERM, 0.22 uF, 10 V, +/- 10%, X7R, 0402; Manufacturer: TDK; Polarized: N; Value: 0.22uF; U/M: EA; Cap_F: 220nF; Value1: Unknown; VDC_V: 10V; TempCo: X5R; TaMin_C: -55°C; TaMax_C: 85°C; Cap_Case: 0402; SizeArea_mm2: 0.5; SizeAreaWB_mm2: 3; SizeX_mm: 1; SizeZ_mm: 0.6; AEC Category: Q200
C100-C104 = CMP-0086447-1: as C61 on sheet PROC073D_PMIC
L1-L3 L7 = CMP-0003427-2: Ferrite Bead, 100 ohm @ 100 MHz, 4 A, 0805; Manufacturer: TDK; Value1: 0.02 ohm; Value: 100 ohm; Imax_A: 4A; DCR_ohm: 0.02; ZTyp@100MHz_Ohm: 100
R1 = CMP-0025884-3: as R195 on sheet PROC073D_PMIC

## Sheet PROC073D_QSPI_Flash_section.SchDoc: QSPI Flash
size 431 x 279 mm; Date: Not shown in title block; ApprovedBy: Not shown in title block; CheckedBy: Not shown in title block; Author: Not shown in title block; CompanyName: Not shown in title block; DrawnBy: Charles F. Oladimeji; Engineer: Not shown in title block; Organization: Not shown in title block; Address1: Not shown in title block; Address2: Not shown in title block; Address3: Not shown in title block; Address4: Not shown in title block; DocumentNumber: 6; Revision: Use project parameter SCH_Rev; SheetNumber: 6; SheetTotal: 13; PageSetup: Record=PageOptions¦CenterHorizontal=True¦CenterVertical=True¦PrintScale=1.00¦XCorrection=1.00¦YCorrection=1.00¦PrintKind=0¦BorderSize=5000000¦LeftOffset=0¦BottomOffset=0¦Orientation=2¦PaperLength=1000¦PaperWidth=1000¦Scale=100¦PaperSource=15¦PrintQuality=600¦MediaType=1¦DitherType=10¦PaperKind=Letter¦PrintScaleMode=1
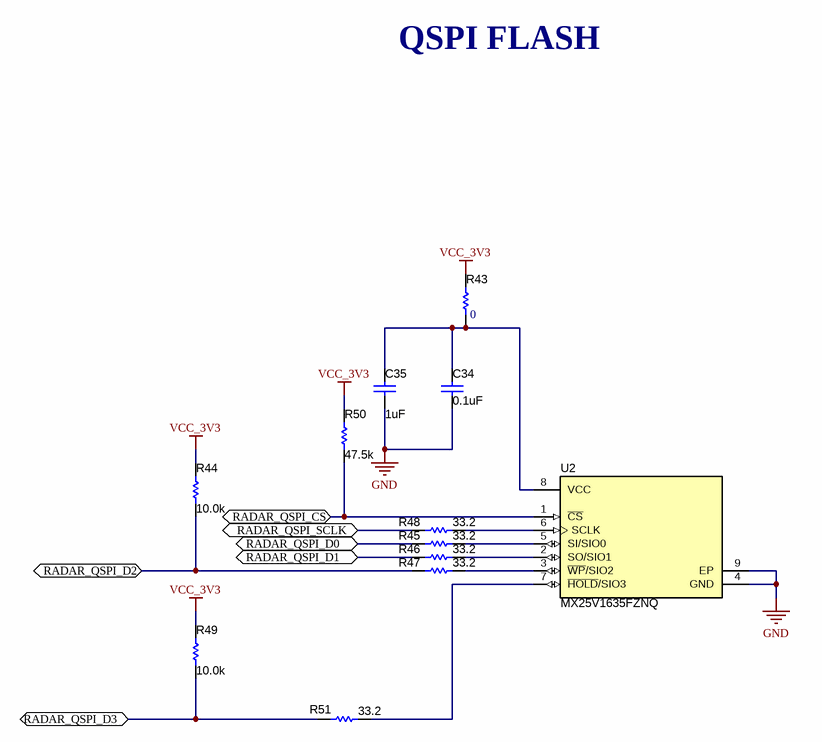
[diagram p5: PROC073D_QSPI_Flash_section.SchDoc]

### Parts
C34  ValueDisplayed: 0.1uF  [0402L]  (hidden comment: CGA2B3X7R1H104K050BB)
C35  ValueDisplayed: 1uF  [0603]  (hidden comment: GCM188R71C105KA64D)
R43  ValueDisplayed: 0  [0402]  (hidden comment: ERJ-2GE0R00X)
R44  ValueDisplayed: 10.0k  [0402L]  (hidden comment: CRCW040210K0FKED)
R45  ValueDisplayed: 33.2  [0201_Silk]  (hidden comment: CRCW020133R2FNED)
R46  ValueDisplayed: 33.2  [0201_Silk]  (hidden comment: CRCW020133R2FNED)
R47  ValueDisplayed: 33.2  [0201_Silk]  (hidden comment: CRCW020133R2FNED)
R48  ValueDisplayed: 33.2  [0201_Silk]  (hidden comment: CRCW020133R2FNED)
R49  ValueDisplayed: 10.0k  [0402L]  (hidden comment: CRCW040210K0FKED)
R50  ValueDisplayed: 47.5k  [0402L]  (hidden comment: CRCW040247K5FKED)
R51  ValueDisplayed: 33.2  [0201_Silk]  (hidden comment: CRCW020133R2FNED)
U2  MX25V1635FZNQ  [WSON-8L_6x5MM_EP]

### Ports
RADAR_QSPI_CS (bidir), RADAR_QSPI_D0 (bidir), RADAR_QSPI_D1 (bidir), RADAR_QSPI_D2 (bidir), RADAR_QSPI_D3 (bidir), RADAR_QSPI_SCLK (bidir)

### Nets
GND: C34.1 C35.1 U2.4(GND) U2.9(EP)
VCC_3V3: R43.2 R44.2 R49.2 R50.1
RADAR_QSPI_CS: R50.2 U2.1(~{CS}) ; port RADAR_QSPI_CS
RADAR_QSPI_D0: R45.2 ; port RADAR_QSPI_D0
RADAR_QSPI_D1: R46.1 ; port RADAR_QSPI_D1
RADAR_QSPI_D2: R44.1 R47.1 ; port RADAR_QSPI_D2
RADAR_QSPI_D3: R49.1 R51.2 ; port RADAR_QSPI_D3
RADAR_QSPI_SCLK: R48.2 ; port RADAR_QSPI_SCLK
NetC34_2: C34.2 C35.2 R43.1 U2.8(VCC)
NetR45_1: R45.1 U2.5(SI/SIO0)
NetR46_2: R46.2 U2.2(SO/SIO1)
NetR47_2: R47.2 U2.3(~{WP}/SIO2)
NetR48_1: R48.1 U2.6(SCLK)
NetR51_1: R51.1 U2.7(~{HOLD}/SIO3)

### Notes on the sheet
- QSPI FLASH

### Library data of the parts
C34 = CMP-0006325-2: CAP, CERM, 0.1 uF, 50 V, +/- 10%, X7R, AEC-Q200 Grade 1, 0402; Manufacturer: TDK; TaMin_C: -55°C; ESR_ohm: 0.039064; Polarized: N; SizeAreaWB_mm2: 3; Value1: 0.039064 ohm; U/M: EA; Value: 0.1uF; TaMax_C: 125°C; SizeZ_mm: 0.6; SizeX_mm: 1; SizeY_mm: 0.5; Cap_Case: 0402; Value2: 50V; AEC Qualified: Y; Cap_F: 100nF; IRMS_A: 8.14669dA; AEC Category: Q200
C35 = CMP-0007136-5: as C18 on sheet PROC073D_Decoupling_caps
R43 = CMP-0026992-3: as R72 on sheet PROC073D_IWR6843_Chip
R44 R49 = CMP-0025958-3: as R152 on sheet PROC073D_IWR6843_Chip
R45-R48 R51 = CMP-0027275-3: RES, 33.2, 1%, 0.05 W, 0201; Manufacturer: Vishay-Dale; Power_W: 50mW; TempCo: 200 ppm/C; Value_Code: 33R2; Value: 33.2; EIA_Code: E96; SizeX_mm: 0.6; SizeY_mm: 0.3; SizeZ_mm: 0.26; Value2: 0.05W; SizeArea_mm2: 0.18; AEC Qualified: N; AEC Category: Q200
R50 = CMP-0026395-2: RES, 47.5 k, 1%, 0.063 W, AEC-Q200 Grade 0, 0402; Manufacturer: Vishay-Dale; Power_W: 63mW; TempCo: 100 ppm/C; Value_Code: 47k5; Value: 47.5k; EIA_Code: E96; SizeX_mm: 1; SizeY_mm: 0.5; SizeZ_mm: 0.6; Value2: 0.063W; AEC Qualified: Y; VDC_V: 50V; AEC Category: Q200; AEC Grade: 0
U2 = CMP-0079267-1: 2.3V-3.6V, 16M-BIT [x 1/x 2/x 4] CMOS FLASH Memory, WSON-8; Manufacturer: Macronix International Co., LTD; SizeArea_mm2: 30; SizeAreaWB_mm2: 56; SizeY_mm: 5; SizeZ_mm: 0.8; SizeX_mm: 6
